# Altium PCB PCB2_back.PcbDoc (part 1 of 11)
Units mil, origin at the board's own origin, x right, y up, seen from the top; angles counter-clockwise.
Board outline 6299 x 3937 mil, 4 copper layers (TopLayer, GROUND, VCC, BottomLayer); 290 components, 470 nets, 2252 pads, 825 vias.
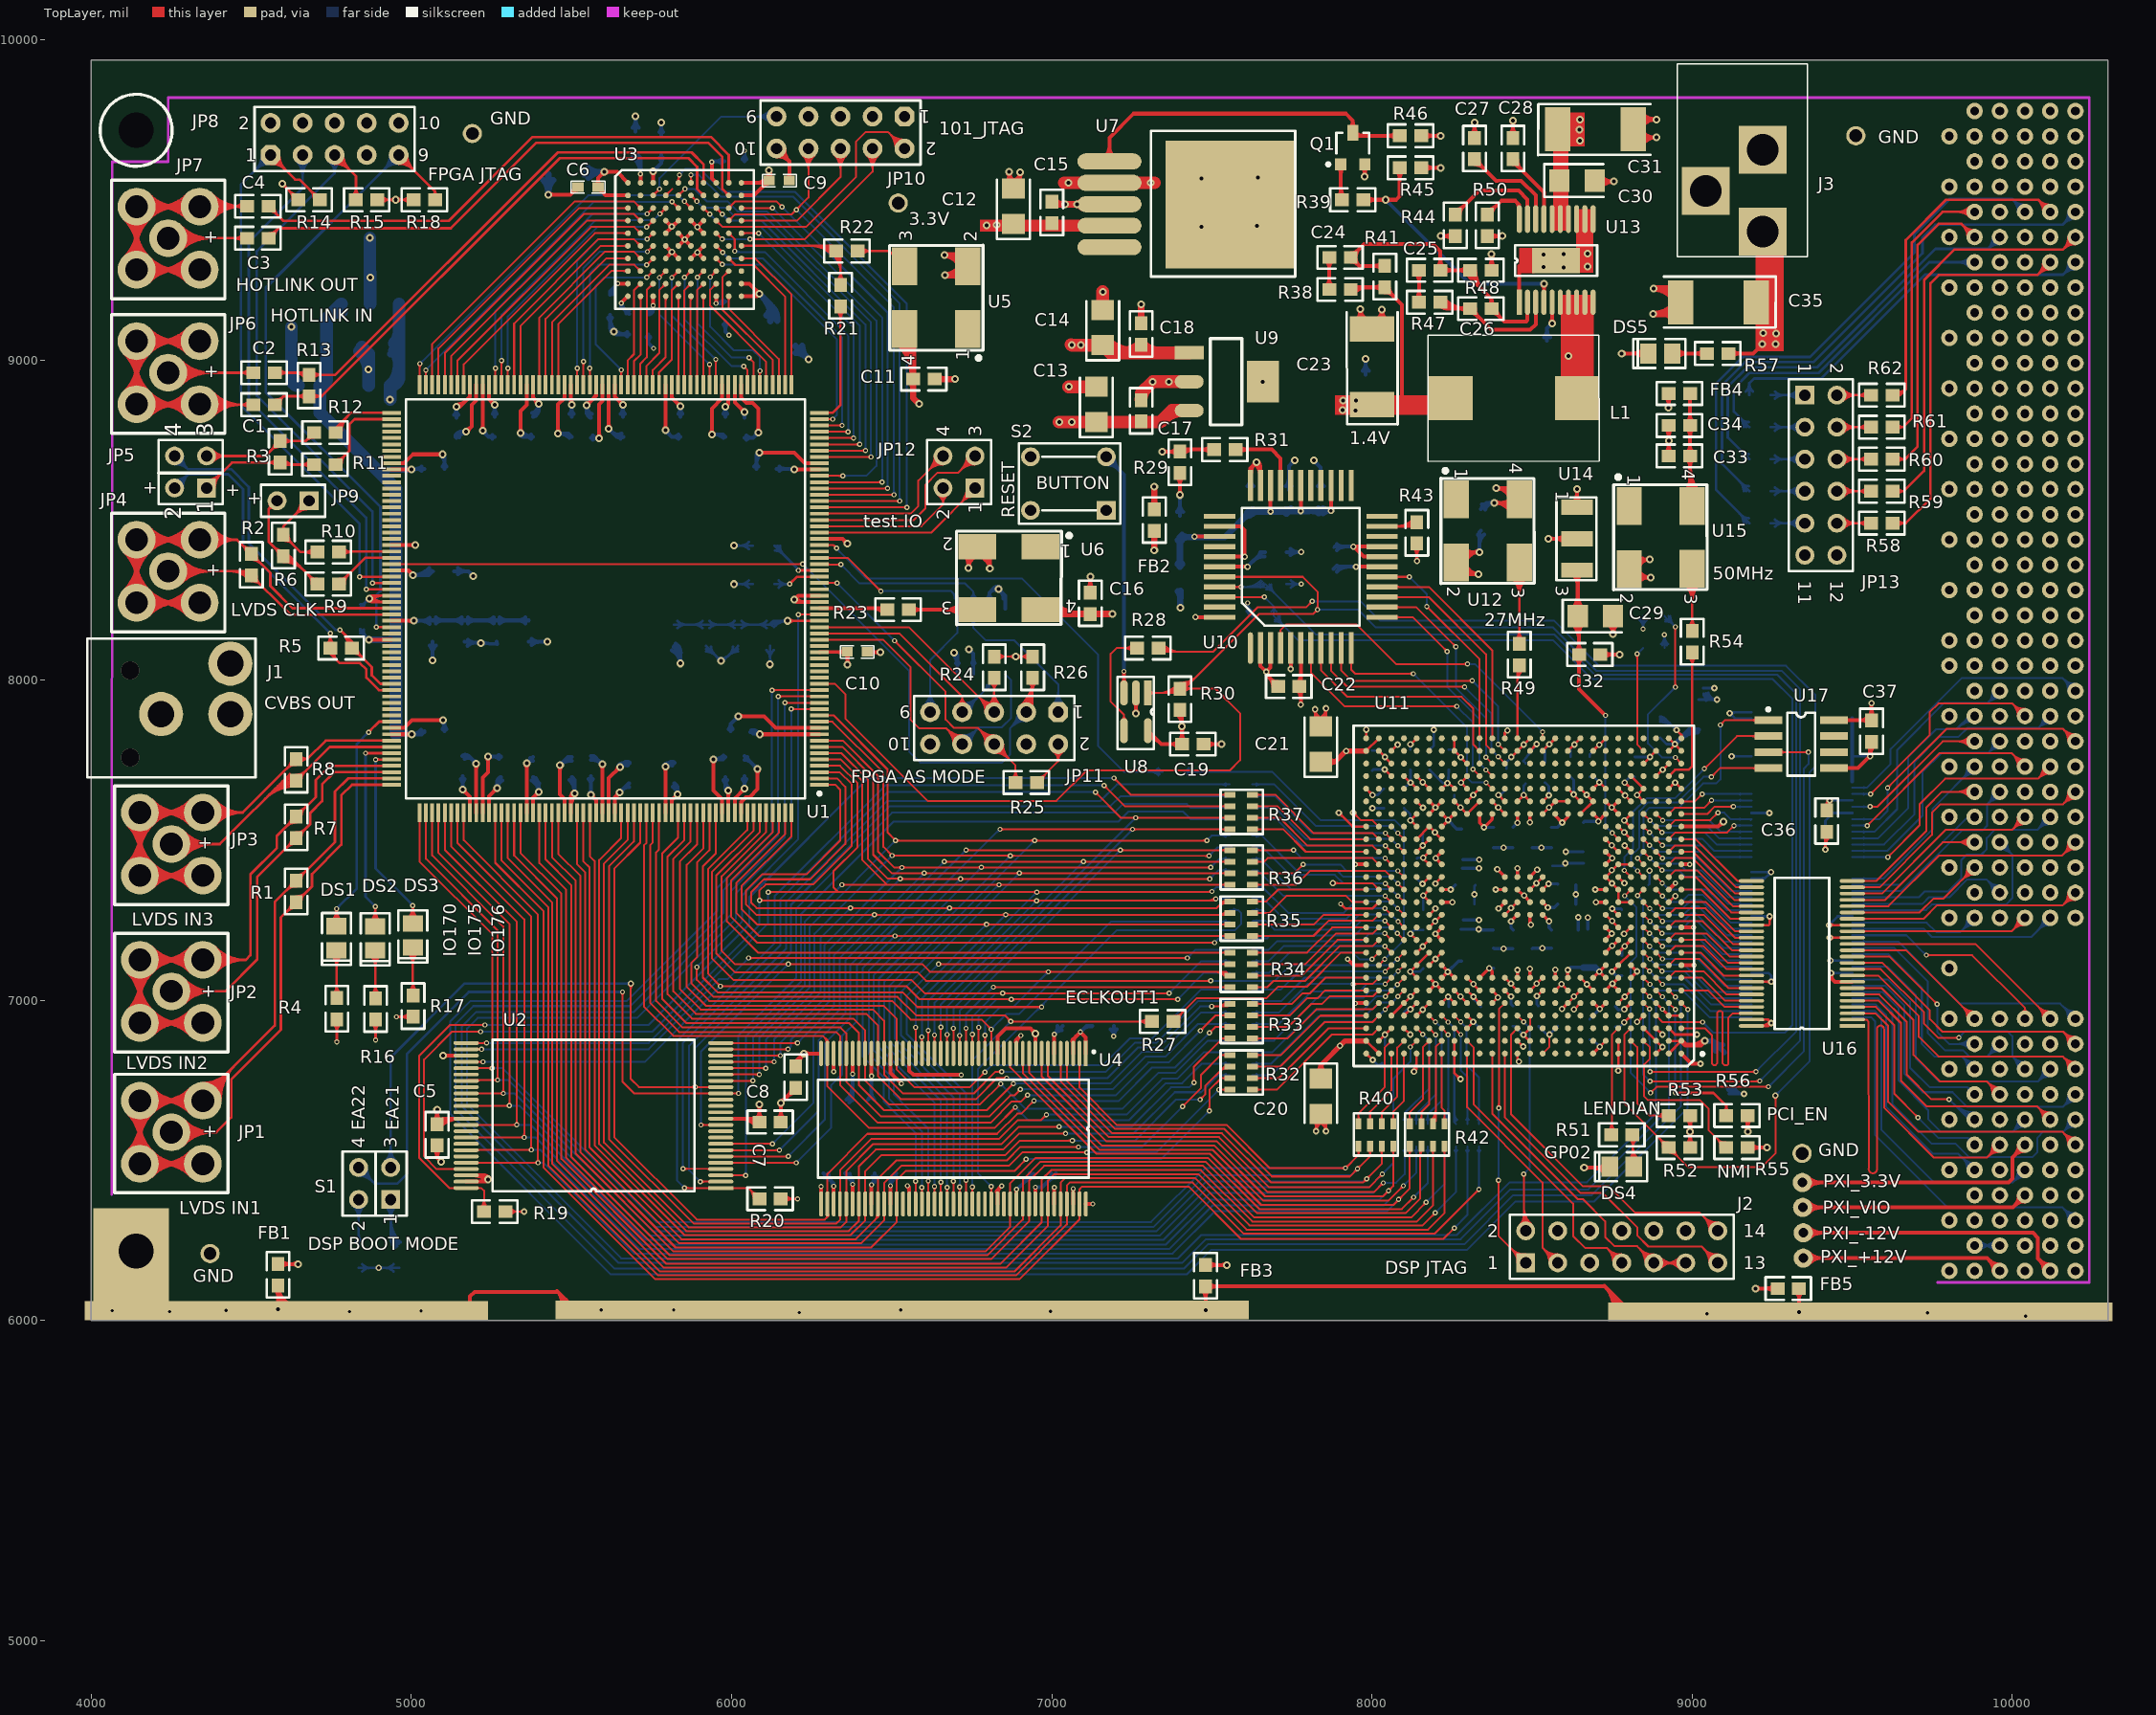
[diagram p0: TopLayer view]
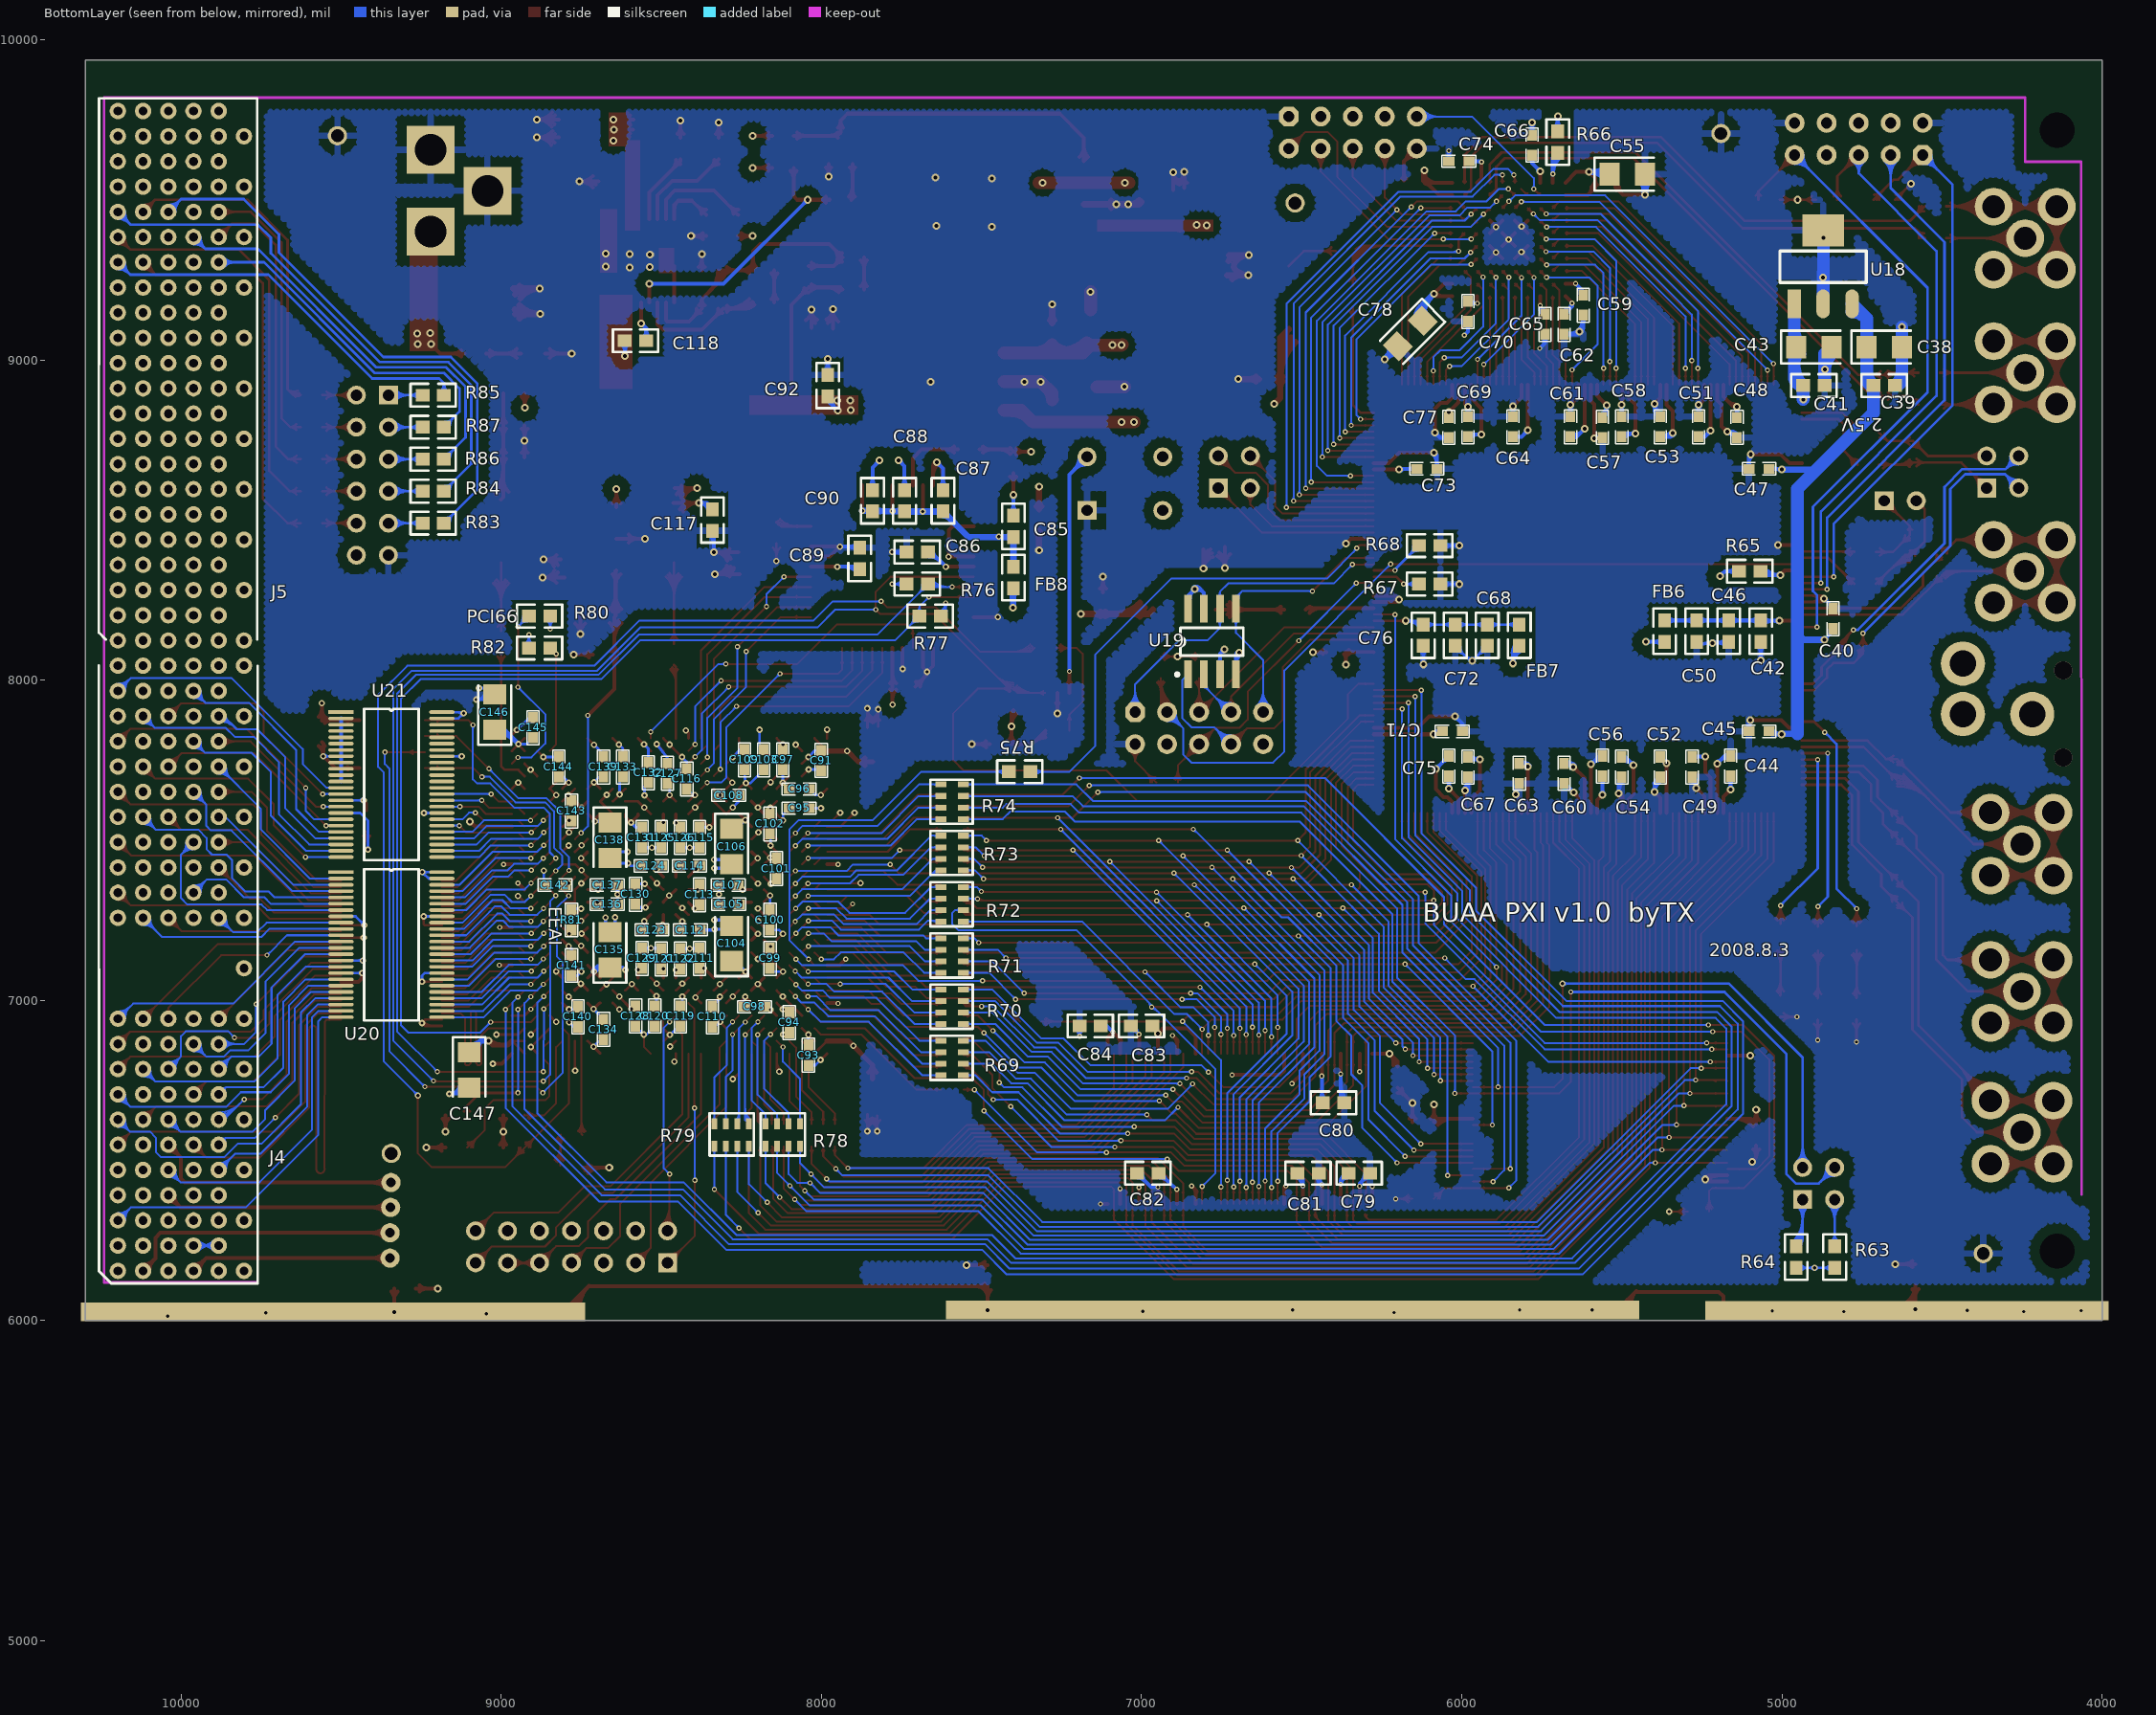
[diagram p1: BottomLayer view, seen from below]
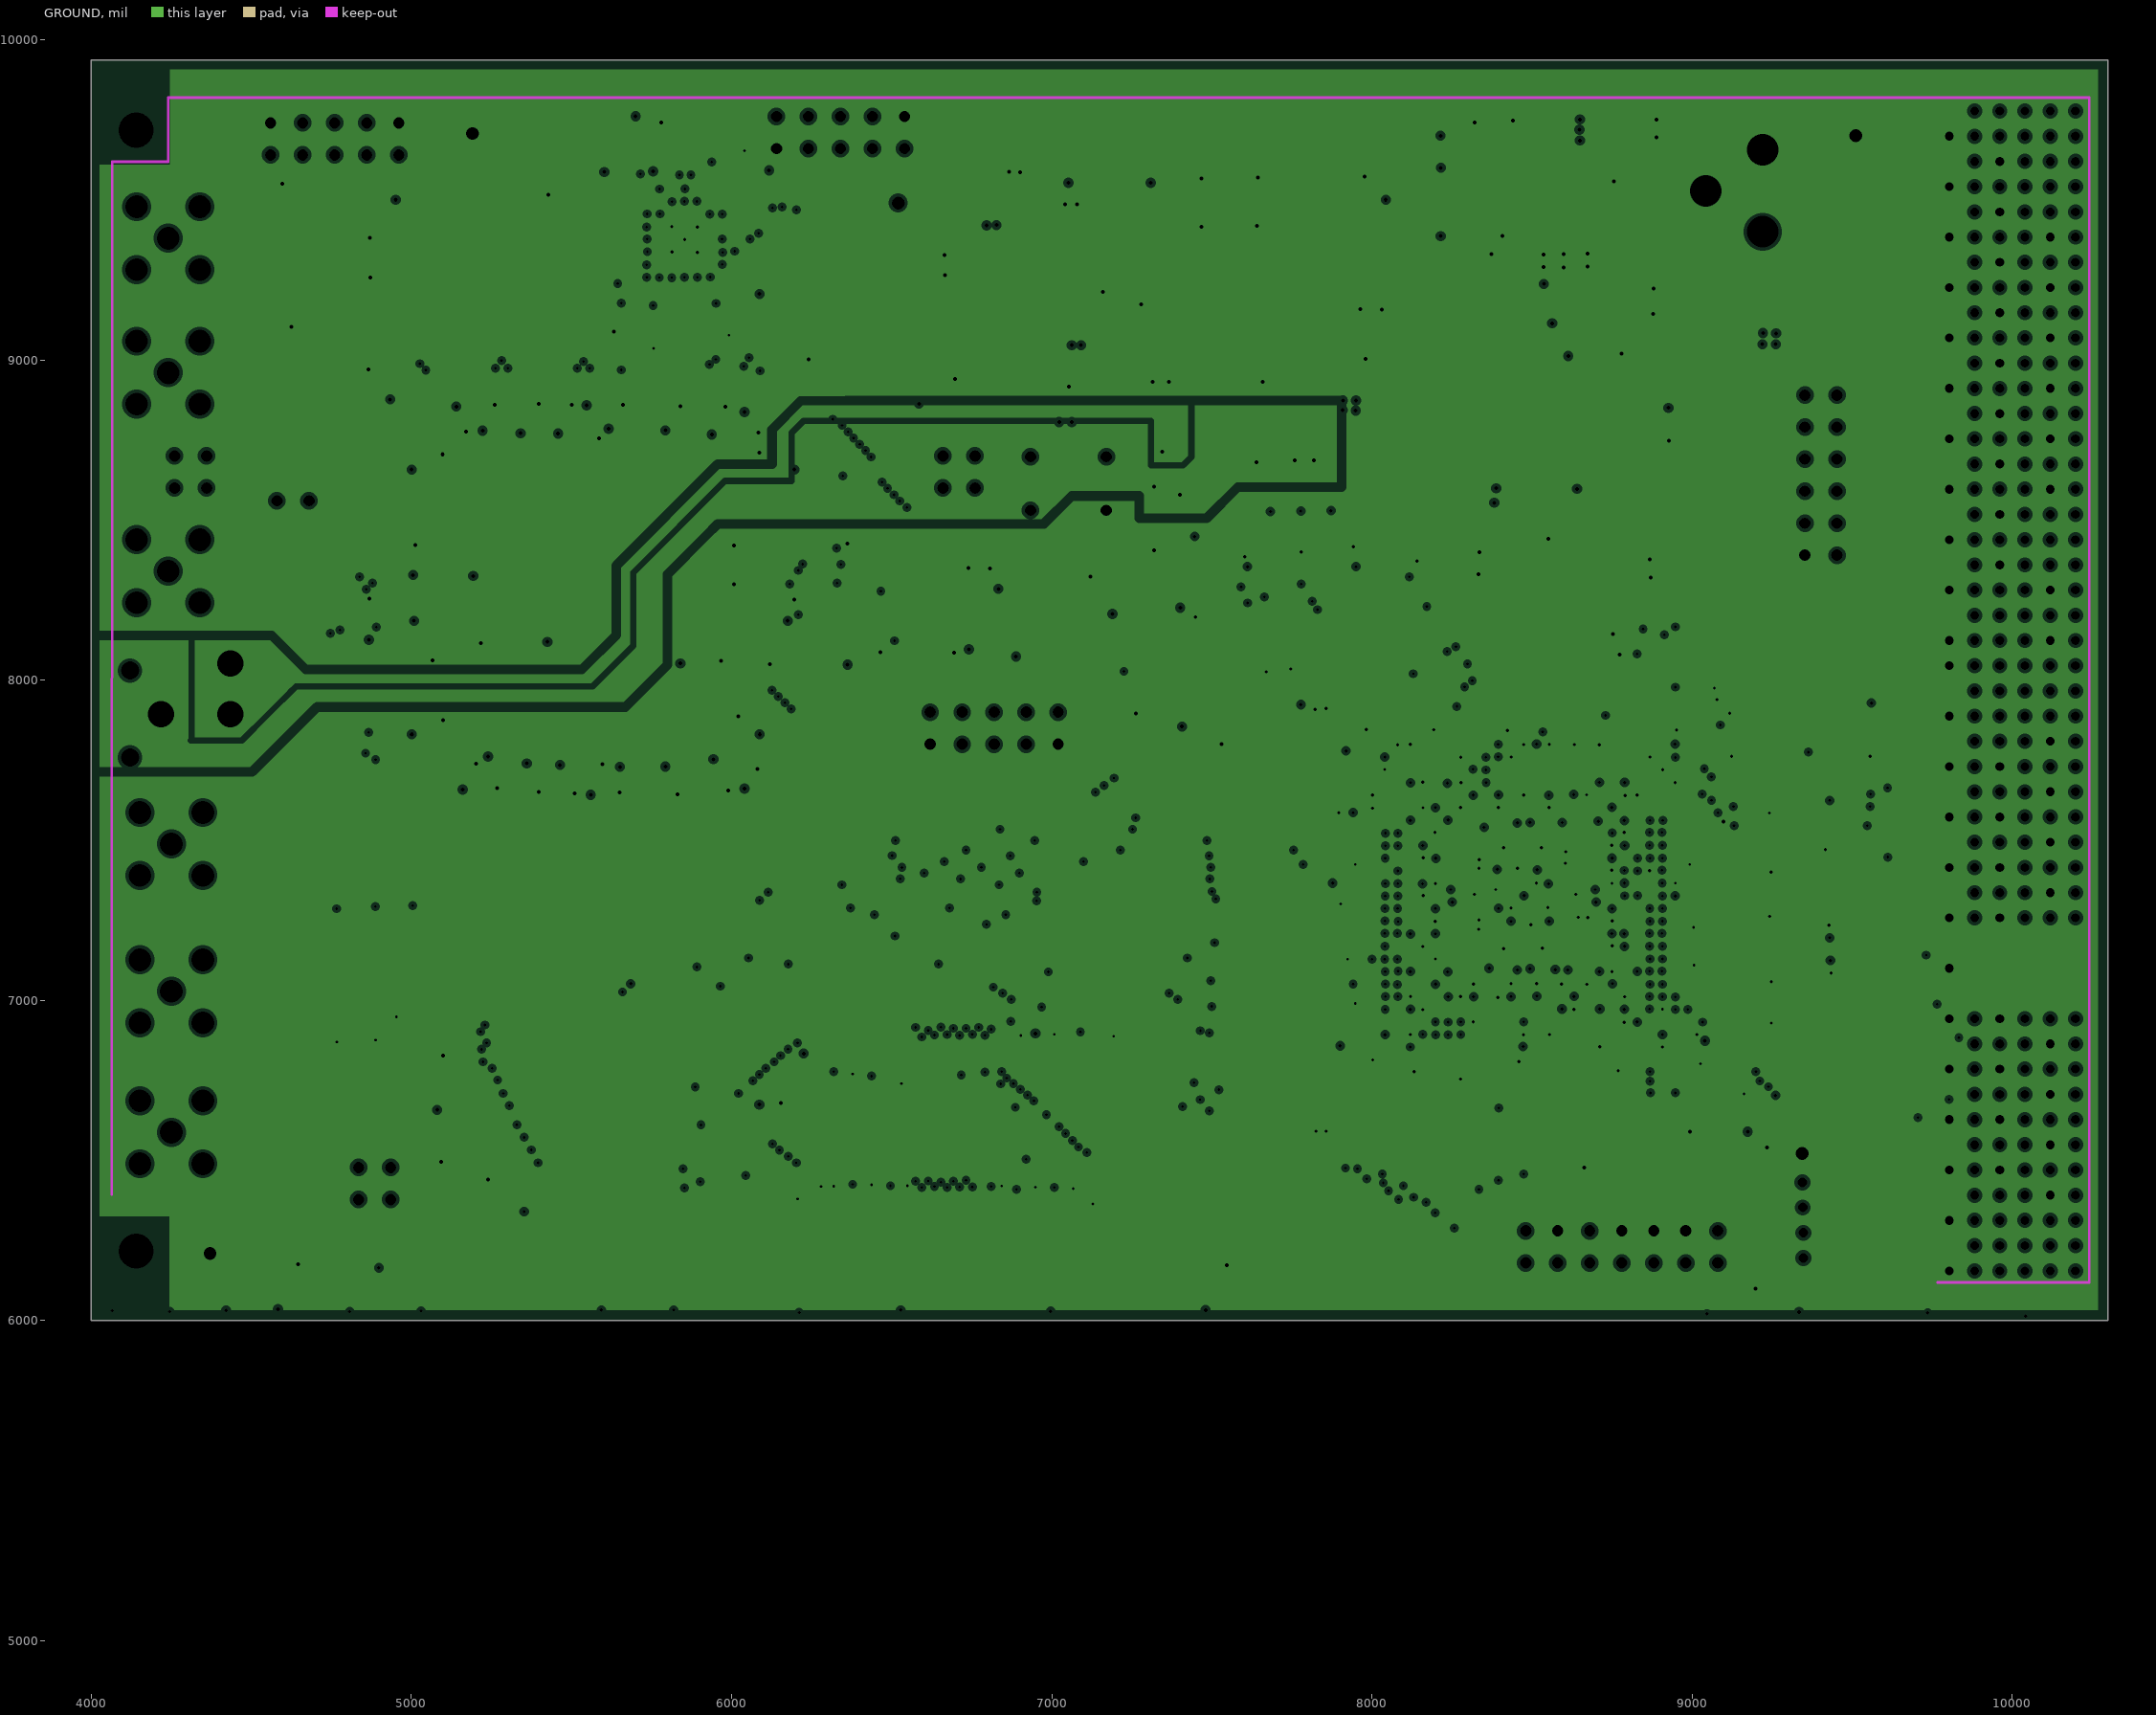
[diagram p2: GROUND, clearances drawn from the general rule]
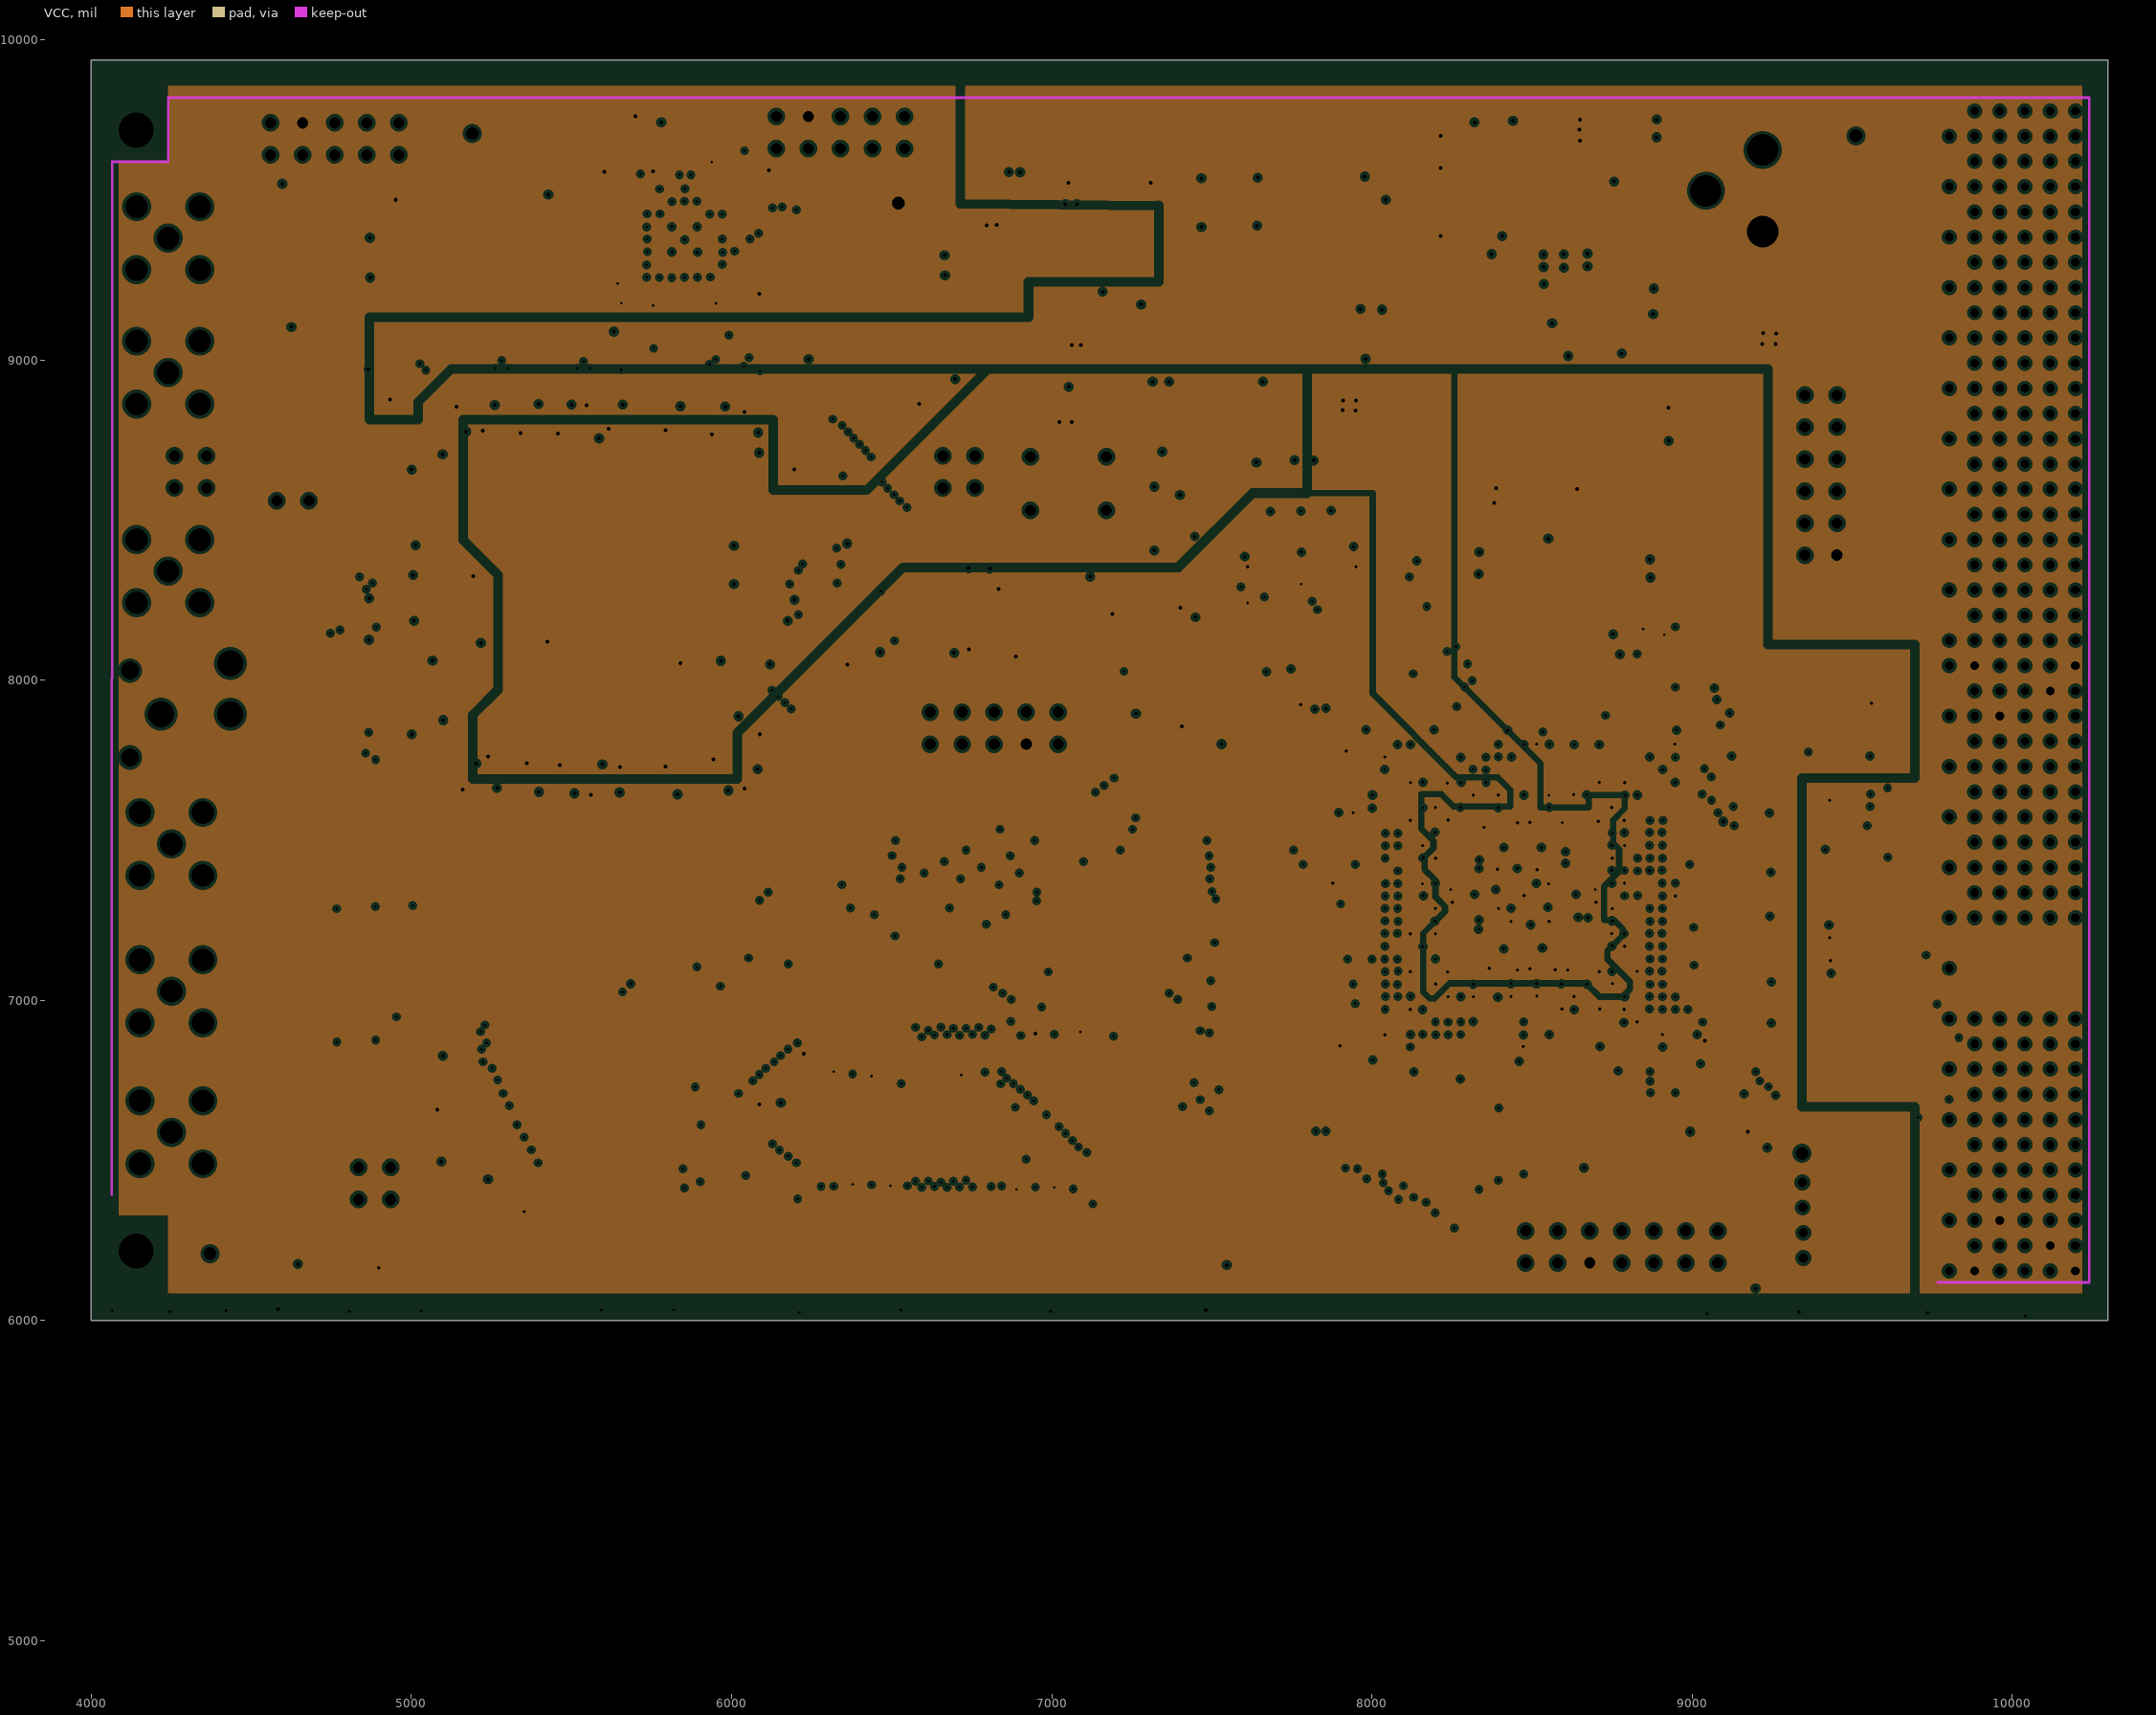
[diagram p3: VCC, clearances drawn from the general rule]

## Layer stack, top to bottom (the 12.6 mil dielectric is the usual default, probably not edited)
TopLayer: signal copper 1.4
Dielectric: core 12.6, FR-4, Dk 4.8
GROUND: plane copper 1.4, net (Multiple Nets)
Dielectric: prepreg 12.6, FR-4, Dk 4.8
VCC: plane copper 1.4, net (Multiple Nets)
Dielectric: core 12.6, FR-4, Dk 4.8
BottomLayer: signal copper 1.4

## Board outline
4000,6000 10299,6000 10299,9937 4000,9937

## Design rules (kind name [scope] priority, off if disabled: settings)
Clearance [All] p1: gap=6
ComponentClearance ComponentClearance_1 [All] p1: gap=10 collisioncheckmode=0
HoleSize HoleSize_1 [All] p1: absolutevalues=TRUE maxlimit=100 minlimit=1 maxpercent=80.000 minpercent=20.000
LayerPairs LayerPairs_1 [All] p1: enforce=TRUE
PasteMaskExpansion PasteMaskExpansion_1 [All] p1: expansion=0
PlaneClearance PlaneClearance_1 [All] p1: clearance=10
PlaneConnect [All] p1: planeconnectstyle=Relief reliefexpansion=15 reliefentries=4 reliefconductorwidth=15.75 reliefairgap=9.84
PolygonConnect PolygonConnect_1 [All] p1: connectstyle=Relief reliefconductorwidth=20 reliefentries=4 polygonreliefangle="90 Angle"
RoutingLayers [All] p1: top layer=Horizontal bottom layer=Vertical
RoutingPriority RoutingPriority_1 [All] p1: routingpriority=0
RoutingTopology RoutingTopology_1 [All] p1: topology=Shortest
RoutingVias [All] p1: holewidth=12 width=24 viastyle="Through Hole" minholewidth=8 minwidth=16 maxholewidth=28 maxwidth=50
ShortCircuit ShortCircuit_1 [All] p1: allowed=FALSE
SolderMaskExpansion SolderMaskExpansion_1 [All] p1: expansion=2
TestPointUsage TestPointUsage_1 [All] p1: valid=0 allowmultiple=FALSE
Testpoint Testpoint_1 [All] p1: side=7 testpointundercomponent=TRUE minsize=40 maxsize=100 preferedsize=60 minholesize=20 maxholesize=40 preferedholesize=32 testpointgrid=1 style=1001 order=-539222988
UnRoutedNet UnRoutedNet_1 [All] p1:
Width [All] p1: maxlimit=40 minlimit=6 preferedwidth=6
7 further rules are at their usual default settings.

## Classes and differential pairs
component class U_Sheet4_DSP2_videoport: C19 C22 C29 C32 C33 C34 C37 C85 C86 C87 C88 C89 C90 C117 DS4 FB2 FB4 FB8 J1 R28 R29 R30 R31 R43 R49 R51 R52 R53 R54 R55 R76 R77 R80 R81 R82 R? S2 U8 U10 U11 U12 U14 U15 U17
component class U_Sheet3_power_clock: C10 C12 C13 C14 C15 C17 C18 C20 C21 C23 C24 C25 C26 C27 C28 C30 C31 C35 C38 C39 C40 C41 C42 C43 C44 C45 C46 C47 C48 C49 C50 C51 C52 C53 C54 C56 C57 C58 C60 C61 C63 C64 C67 C68 C69 C71 C72 C73 C75 C76 C77 C91 C92 C93 C94 C95 C96 C97 C98 C99 C100 C101 C102 C103 C104 C105 C106 C107 C108 C109 C110 C111 C112 C113 C114 C115 C116 C118 C119 C120 C121 C122 C123 C124 C125 C126 C127 C128 C129 C130 C131 C132 C133 C134 C135 C136 C137 C138 C139 C140 C141 C142 C143 C144 C145 C146 C147 DS5 FB6 FB7 J3 L1 Q1 R38 R39 R41 R44 R45 R46 R47 R48 R50 R57 U7 U9 U13 U18
component class U_Sheet2_PXI: C36 J4 J5 JP13 R56 R58 R59 R60 R61 R62 R83 R84 R85 R86 R87 U16 U20 U21
component class U_Sheet2_DSP_EMIF: C5 C7 C8 C79 C80 C81 C82 C83 C84 J2 R19 R20 R27 R32 R33 R34 R35 R36 R37 R40 R42 R63 R64 R69 R70 R71 R72 R73 R74 R78 R79 S1 U2 U4
component class U_Sheet1_FPGA2: C1 C2 C3 C4 C6 C9 C11 C16 C55 C59 C62 C65 C66 C70 C74 C78 DS1 DS2 DS3 FB1 FB3 FB5 JP1 JP2 JP3 JP4 JP5 JP6 JP7 JP8 JP9 JP10 JP11 JP12 L2 R1 R2 R3 R4 R5 R6 R7 R8 R9 R10 R11 R12 R13 R14 R15 R16 R17 R18 R21 R22 R23 R24 R25 R26 R65 R66 R67 R68 R75 U1 U3 U5 U6 U19

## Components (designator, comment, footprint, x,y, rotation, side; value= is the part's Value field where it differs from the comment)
C1 "Cap" C1608-0603 4540,8860 r180 top
C2 "Cap" C1608-0603 4540,8960 r180 top
C3 "Cap" C1608-0603 4520,9380 r180 top
C4 "Cap" C1608-0603 4520,9480 r180 top
C5 "Cap" C1608-0603 5080,6580 r90 top (schematic designator C19)
C6 "Cap" 0603 5520,9540 r0 top (schematic designator C9)
C7 "Cap" C1608-0603 6120,6620 r0 top (schematic designator C27)
C8 "Cap" C1608-0603 6200,6760 r90 top (schematic designator C20)
C9 "Cap" 0603 6180,9560 r180 top (schematic designator C7)
C10 "Cap" 0603 6361,8088 r0 top (schematic designator C104)
C11 "Cap" C1608-0603 6600,8940 r180 top (schematic designator C18)
C12 "Cap Pol1" CC3216-1206 6880,9480 r90 top (schematic designator C135)
C13 "Cap Pol1" CC3216-1206 7139,8861 r90 top (schematic designator C137)
C14 "Cap Pol1" CC3216-1206 7159,9101 r90 top (schematic designator C136)
C15 "Cap" C1608-0603 7000,9460 r270 top (schematic designator C95)
C16 "Cap" C1608-0603 7120,8240 r270 top (schematic designator C17)
C17 "Cap" C1608-0603 7279,8841 r270 top (schematic designator C125)
C18 "Cap" C1608-0603 7279,9081 r270 top (schematic designator C96)
C19 "Cap" C1608-0603 7440,7800 r180 top (schematic designator C133)
C20 "Cap Pol2" CC3216-1206 7840,6700 r270 top (schematic designator C150)
C21 "Cap Pol2" CC3216-1206 7840,7800 r90 top (schematic designator C147)
C22 "Cap" C1608-0603 7740,7980 r0 top (schematic designator C156)
C23 "Cap Pol1" CC6032 8000,8860 r90 top (schematic designator C138)
C24 "Cap" C1608-0603 7900,9320 r180 top (schematic designator C122)
C25 "Cap" C1608-0603 8180,9280 r180 top (schematic designator C113)
C26 "Cap" C1608-0603 8340,9160 r180 top (schematic designator C118)
C27 "Cap" C1608-0603 8320,9660 r270 top (schematic designator C54)
C28 "Cap" C1608-0603 8440,9660 r270 top (schematic designator C64)
C29 "Cap Pol2" CC3216-1206 8697.68,8200 r0 top (schematic designator C164)
C30 "Cap Pol2" CC3216-1206 8640,9560 r0 top (schematic designator C146)
C31 "Cap Pol1" CC6032 8580,9720 r0 top (schematic designator C134)
C32 "Cap" C1608-0603 8680,8080 r180 top (schematic designator C163)
C33 "Cap" C1608-0603 8960,8700 r0 top (schematic designator C161)
C34 "Cap" C1608-0603 8960,8795 r0 top (schematic designator C160)
C35 "Cap Pol1" CC6032 9200,9180 r180 top (schematic designator C140)
C36 "Cap" C1608-0603 9420,7560 r90 top (schematic designator C166)
C37 "Cap" C1608-0603 9560,7840 r90 top (schematic designator C162)
C38 "Cap Pol1" CC3216-1206 4680,9040 r180 bottom (schematic designator C143)
C39 "Cap" C1608-0603 4680,8920 r0 bottom (schematic designator C132)
C40 "Cap" 0603 4840,8160 r90 bottom (schematic designator C108)
C41 "Cap" C1608-0603 4900,8920 r0 bottom (schematic designator C127)
C42 "Cap" C1608-0603 5066,8153 r90 bottom (schematic designator C131)
C43 "Cap Pol1" CC3216-1206 4900,9040 r180 bottom (schematic designator C139)
C44 "Cap" 0603 5160,7700 r90 bottom (schematic designator C98)
C45 "Cap" 0603 5040,7840 r0 bottom (schematic designator C97)
C46 "Cap" C1608-0603 5166,8153 r90 bottom (schematic designator C129)
C47 "Cap" 0603 5040,8660 r0 bottom (schematic designator C103)
C48 "Cap" 0603 5140,8820 r270 bottom (schematic designator C110)
C49 "Cap" 0603 5280,7760 r270 bottom (schematic designator C100)
C50 "Cap Pol1" C1608-0603 5266,8153 r270 bottom (schematic designator C142)
C51 "Cap" 0603 5260,8760 r90 bottom (schematic designator C124)
C52 "Cap" 0603 5380,7760 r270 bottom (schematic designator C106)
C53 "Cap" 0603 5380,8760 r90 bottom (schematic designator C112)
C54 "Cap" 0603 5500,7760 r270 bottom (schematic designator C111)
C55 "Cap Pol2" CC3216-1206 5482.31,9580 r180 bottom (schematic designator C14)
C56 "Cap" 0603 5560,7700 r90 bottom (schematic designator C109)
C57 "Cap" 0603 5560,8820 r270 bottom (schematic designator C114)
C58 "Cap" 0603 5500,8760 r90 bottom (schematic designator C101)
C59 "Cap" 0603 5620,9140 r90 bottom (schematic designator C10)
C60 "Cap" 0603 5680,7740 r270 bottom (schematic designator C116)
C61 "Cap" 0603 5660,8760 r90 bottom (schematic designator C121)
C62 "Cap" 0603 5680,9080 r90 bottom (schematic designator C6)
C63 "Cap" 0603 5820,7740 r270 bottom (schematic designator C123)
C64 "Cap" 0603 5840,8760 r90 bottom (schematic designator C117)
C65 "Cap" 0603 5740,9080 r90 bottom (schematic designator C5)
C66 "Cap" 0603 5780,9702 r270 bottom (schematic designator C11)
C67 "Cap" 0603 5980,7760 r270 bottom (schematic designator C120)
C68 "Cap" C1608-0603 5920,8140 r90 bottom (schematic designator C128)
C69 "Cap" 0603 5980,8760 r90 bottom (schematic designator C107)
C70 "Cap" 0603 5980,9120 r90 bottom (schematic designator C16)
C71 "Cap" 0603 6060,7840 r180 bottom (schematic designator C119)
C72 "Cap Pol1" C1608-0603 6020,8140 r270 bottom (schematic designator C141)
C73 "Cap" 0603 6140,8660 r180 bottom (schematic designator C115)
C74 "Cap" 0603 6040,9620 r180 bottom (schematic designator C8)
C75 "Cap" 0603 6040,7700 r90 bottom (schematic designator C105)
C76 "Cap" C1608-0603 6120,8140 r90 bottom (schematic designator C130)
C77 "Cap" 0603 6040,8820 r270 bottom (schematic designator C99)
C78 "Cap Pol2" CC3216-1206 6160,9082.32 r315 bottom (schematic designator C15)
C79 "Cap" C1608-0603 6320,6460 r0 bottom (schematic designator C24)
C80 "Cap" C1608-0603 6400,6680 r0 bottom (schematic designator C21)
C81 "Cap" C1608-0603 6480,6460 r0 bottom (schematic designator C25)
C82 "Cap" C1608-0603 6980,6460 r180 bottom (schematic designator C26)
C83 "Cap" C1608-0603 7000,6920 r180 bottom (schematic designator C23)
C84 "Cap" C1608-0603 7160,6920 r180 bottom (schematic designator C22)
C85 "Cap" C1608-0603 7400,8480 r270 bottom (schematic designator C159)
C86 "Cap" C1608-0603 7700,8400 r180 bottom (schematic designator C158)
C87 "Cap" C1608-0603 7620,8560 r270 bottom (schematic designator C157)
C88 "Cap" C1608-0603 7740,8560 r270 bottom (schematic designator C155)
C89 "Cap" C1608-0603 7880,8380 r270 bottom (schematic designator C154)
C90 "Cap" C1608-0603 7840,8560 r270 bottom (schematic designator C153)
C91 "Cap" 0603 8000,7780 r270 bottom (schematic designator C49)
C92 "Cap" C1608-0603 7980,8920 r270 bottom (schematic designator C126)
C93 "Cap" 0603 8040,6860 r270 bottom (schematic designator C75)
C94 "Cap" 0603 8100,6962 r270 bottom (schematic designator C74)
C95 "Cap" 0603 8100,7600 r180 bottom (schematic designator C57)
C96 "Cap" 0603 8100,7660 r180 bottom (schematic designator C65)
C97 "Cap" 0603 8120,7720 r90 bottom (schematic designator C58)
C98 "Cap" 0603 8240,6980 r180 bottom (schematic designator C73)
C99 "Cap" 0603 8160,7100 r90 bottom (schematic designator C69)
C100 "Cap" 0603 8160,7220 r90 bottom (schematic designator C68)
C101 "Cap" 0603 8140,7380 r90 bottom (schematic designator C67)
C102 "Cap" 0603 8160,7520 r90 bottom (schematic designator C66)
C103 "Cap" 0603 8180,7720 r90 bottom (schematic designator C40)
C104 "Cap Pol2" CC3216-1206 8280,7177.69 r90 bottom (schematic designator C149)
C105 "Cap" 0603 8320,7300 r180 bottom (schematic designator C63)
C106 "Cap Pol2" CC3216-1206 8280,7480 r270 bottom (schematic designator C148)
C107 "Cap" 0603 8260,7360 r0 bottom (schematic designator C71)
C108 "Cap" 0603 8320,7640 r180 bottom (schematic designator C59)
C109 "Cap" 0603 8240,7720 r90 bottom (schematic designator C56)
C110 "Cap" 0603 8340,6980 r270 bottom (schematic designator C76)
C111 "Cap" 0603 8380,7100 r90 bottom (schematic designator C79)
C112 "Cap" 0603 8378,7220 r0 bottom (schematic designator C78)
C113 "Cap" 0603 8380,7298 r90 bottom (schematic designator C72)
C114 "Cap" 0603 8380,7420 r0 bottom (schematic designator C60)
C115 "Cap" 0603 8380,7540 r270 bottom (schematic designator C53)
C116 "Cap" 0603 8420,7660 r90 bottom (schematic designator C48)
C117 "Cap" C1608-0603 8340,8500 r90 bottom (schematic designator C165)
C118 "Cap" C1608-0603 8580,9060 r0 bottom (schematic designator C102)
C119 "Cap" 0603 8440,6982 r270 bottom (schematic designator C83)
C120 "Cap" 0603 8520,6982 r270 bottom (schematic designator C77)
C121 "Cap" 0603 8500,7098 r90 bottom (schematic designator C81)
C122 "Cap" 0603 8440,7098 r90 bottom (schematic designator C80)
C123 "Cap" 0603 8560,7220 r180 bottom (schematic designator C70)
C124 "Cap" 0603 8500,7420 r0 bottom (schematic designator C52)
C125 "Cap" 0603 8500,7540 r270 bottom (schematic designator C43)
C126 "Cap" 0603 8440,7540 r270 bottom (schematic designator C42)
C127 "Cap" 0603 8480,7740 r270 bottom (schematic designator C37)
C128 "Cap" 0603 8580,6982 r270 bottom (schematic designator C82)
C129 "Cap" 0603 8560,7100 r90 bottom (schematic designator C87)
C130 "Cap" 0603 8580,7300 r90 bottom (schematic designator C90)
C131 "Cap" 0603 8560,7540 r270 bottom (schematic designator C51)
C132 "Cap" 0603 8540,7680 r90 bottom (schematic designator C46)
C133 "Cap" 0603 8620,7698 r90 bottom (schematic designator C39)
C134 "Cap" 0603 8680,6940 r270 bottom (schematic designator C86)
C135 "Cap Pol2" CC3216-1206 8660,7157.69 r90 bottom (schematic designator C151)
C136 "Cap" 0603 8700,7300 r180 bottom (schematic designator C50)
C137 "Cap" 0603 8700,7360 r180 bottom (schematic designator C44)
C138 "Cap Pol2" CC3216-1206 8660,7500 r270 bottom (schematic designator C145)
C139 "Cap" 0603 8680,7698 r90 bottom (schematic designator C38)
C140 "Cap" 0603 8760,6980 r270 bottom (schematic designator C85)
C141 "Cap" 0603 8780,7140 r270 bottom (schematic designator C84)
C142 "Cap" 0603 8800,7360 r0 bottom (schematic designator C47)
C143 "Cap" 0603 8780,7560 r90 bottom (schematic designator C55)
C144 "Cap" 0603 8820,7698 r90 bottom (schematic designator C41)
C145 "Cap" 0603 8900,7820 r90 bottom (schematic designator C45)
C146 "Cap Pol2" CC3216-1206 9020,7900 r90 bottom (schematic designator C144)
C147 "Cap Pol2" CC3216-1206 9100,6782.31 r270 bottom (schematic designator C152)
DS1 "LED2" "SMD _LED" 4766,7194 r90 top (schematic designator DS3)
DS2 "LED2" "SMD _LED" 4887,7193 r90 top
DS3 "LED2" "SMD _LED" 5004,7202 r90 top (schematic designator DS1)
DS4 "LED3" "SMD _LED" 8780,6480 r0 top (schematic designator DS9)
DS5 "LED3" "SMD _LED" 8900,9020 r0 top (schematic designator DS6)
FB1 "FB" C1608-0603 4583,6143 r90 top (schematic designator FB8)
FB2 "BLM18PG121SN1" C1608-0603 7320,8500 r270 top (schematic designator FB5)
FB3 "FB" C1608-0603 7480,6140 r90 top (schematic designator FB7)
FB4 "BLM18PG121SN1" C1608-0603 8960,8895 r0 top (schematic designator FB3)
FB5 "FB" C1608-0603 9300,6100 r180 top (schematic designator FB6)
FB6 "FB" C1608-0603 5366,8153 r90 bottom (schematic designator FB2)
FB7 "FB" C1608-0603 5820,8140 r90 bottom (schematic designator FB1)
FB8 "BLM18PG121SN1" C1608-0603 7400,8320 r270 bottom (schematic designator FB4)
J1 "RCA" RCA 4260,7940 r0 top (schematic designator J4)
J2 "Header 7X2 JTAG" HDR2X7 8480,6180 r0 top (schematic designator J1)
J3 "PWP_CON" POWER_CON 9220,9400 r90 top
J4 "352068-1" PCI2-H123 10000,7100.06 r270 bottom (schematic designator J2)
J5 "352152-1" PCI2-H121 10000,8950.46 r270 bottom
JP1 "Header 2" SMA 4250,6588 r0 top
JP2 "Header 2" SMA 4250,7028 r0 top
JP3 "Header 2" SMA 4250,7488 r0 top (schematic designator JP7)
JP4 "Header 2" SMA 4240,8340 r0 top (schematic designator JP11)
JP5 "Header 2X2" HDR2X2 4360,8600 r90 top (schematic designator JP10)
JP6 "Header 2" SMA 4240,8960 r0 top (schematic designator JP8)
JP7 "Header 2" SMA 4240,9380 r0 top (schematic designator JP9)
JP8 "JTAG" HDR2X5 4560,9640 r0 top (schematic designator JP4)
JP9 "Header 2" HDR1X2 4680,8560 r180 top (schematic designator JP13)
JP10 "101_JTAG" HDR2X5 6540,9760 r180 top (schematic designator JP3)
JP11 "AS mode" HDR2X5 7020,7900 r180 top (schematic designator JP5)
JP12 "Header 2X2" HDR2X2 6760,8600 r90 top
JP13 "Header 6X2" HDR2X6 9352,8890 r270 top (schematic designator JP6)
L1 "Inductor Iron" L44.7uH 8640,8880 r180 top
Q1 "QNPN3904" "SO-G3 for NPN" 7940,9660 r0 top
R1 "Res2" C1608-0603 4640,7340 r270 top (schematic designator R43)
R2 "Res2" C1608-0603 4500,8360 r270 top (schematic designator R4)
R3 "Res2" C1608-0603 4590,8713 r270 top (schematic designator R1)
R4 "Res2" C1608-0603 4767,6974 r270 top (schematic designator R19)
R5 "Res2" C1608-0603 4780,8100 r180 top (schematic designator R46)
R6 "Res2" C1608-0603 4600,8420 r270 top (schematic designator R5)
R7 "Res2" C1608-0603 4640,7540 r270 top (schematic designator R42)
R8 "Res2" C1608-0603 4640,7720 r270 top (schematic designator R77)
R9 "Res2" C1608-0603 4740,8300 r0 top (schematic designator R6)
R10 "Res2" C1608-0603 4740,8400 r0 top (schematic designator R7)
R11 "Res2" C1608-0603 4730,8673 r0 top (schematic designator R2)
R12 "Res2" C1608-0603 4730,8773 r0 top (schematic designator R3)
R13 "Res2" C1608-0603 4680,8920 r270 top (schematic designator R11)
R14 "Res2" C1608-0603 4680,9500 r0 top (schematic designator R17)
R15 "Res2" C1608-0603 4860,9500 r0 top (schematic designator R16)
R16 "Res2" C1608-0603 4888,6973 r270 top (schematic designator R18)
R17 "Res2" C1608-0603 5005,6982 r270 top (schematic designator R15)
R18 "Res2" C1608-0603 5040,9500 r180 top (schematic designator R14)
R19 "Res1" CR1608-0603 5260,6340 r0 top (schematic designator R58)
R20 "Res1" CR1608-0603 6120,6380 r180 top (schematic designator R59)
R21 "Res2" C1608-0603 6340,9200 r270 top (schematic designator R13)
R22 "Res2" C1608-0603 6360,9340 r180 top (schematic designator R25)
R23 "Res2" C1608-0603 6520,8220 r180 top (schematic designator R24)
R24 "Res2" C1608-0603 6820,8040 r90 top (schematic designator R27)
R25 "Res2" C1608-0603 6920,7680 r180 top (schematic designator R28)
R26 "Res2" C1608-0603 6940,8040 r90 top
R27 "Res1" CR1608-0603 7346,6934 r180 top (schematic designator R55)
R28 "Res1" CR1608-0603 7300,8100 r0 top (schematic designator R81)
R29 "Res1" CR1608-0603 7400,8680 r90 top (schematic designator R41)
R30 "Res1" CR1608-0603 7400,7940 r270 top (schematic designator R71)
R31 "Res1" CR1608-0603 7540,8720 r180 top (schematic designator R40)
R32 "R0604_4" R0603_4 7626,6721 r180 top (schematic designator R38)
R33 "R0604_4" R0603_4 7626,6881 r180 top (schematic designator R37)
R34 "R0604_4" R0603_4 7626,7041 r180 top (schematic designator R30)
R35 "R0604_4" R0603_4 7626,7201 r180 top (schematic designator R54)
R36 "R0604_4" R0603_4 7626,7361 r180 top (schematic designator R49)
R37 "R0604_4" R0603_4 7626,7534 r180 top (schematic designator R51)
R38 "Res1" CR1608-0603 7900,9220 r0 top (schematic designator R69)
R39 "Res3" CR1608-0603 7940,9500 r0 top (schematic designator R72)
R40 "R0604_4" R0603_4 8066,6614 r270 top (schematic designator R31)
R41 "Res1" CR1608-0603 8040,9260 r270 top (schematic designator R70)
R42 "R0604_4" R0603_4 8226,6614 r270 top (schematic designator R32)
R43 "Res1" CR1608-0603 8140,8460 r270 top (schematic designator R39)
R44 "Res1" CR1608-0603 8260,9420 r270 top (schematic designator R66)
R45 "Res1" CR1608-0603 8120,9600 r180 top (schematic designator R64)
R46 "Res3" CR1608-0603 8120,9700 r0 top (schematic designator R73)
R47 "Res1" CR1608-0603 8180,9180 r0 top (schematic designator R68)
R48 "Res1" CR1608-0603 8340,9280 r180 top (schematic designator R67)
R49 "Res1" CR1608-0603 8460,8080 r270 top (schematic designator R76)
R50 "Res1" CR1608-0603 8360,9420 r90 top (schematic designator R65)
R51 "Res1" CR1608-0603 8780,6580 r0 top (schematic designator R86)
R52 "Res1" CR1608-0603 8960,6540 r180 top (schematic designator R83)
R53 "Res1" CR1608-0603 8960,6640 r180 top (schematic designator R84)
R54 "Res1" CR1608-0603 9000,8120 r270 top (schematic designator R82)
R55 "Res1" CR1608-0603 9140,6540 r180 top (schematic designator R79)
R56 "Res1" CR1608-0603 9140,6640 r0 top (schematic designator R61)
R57 "Res2" CR1608-0603 9080,9020 r0 top (schematic designator R62)
R58 "Res1" CR1608-0603 9592,8490 r180 top (schematic designator R91)
R59 "Res1" CR1608-0603 9592,8590 r180 top (schematic designator R90)
R60 "Res1" CR1608-0603 9592,8690 r180 top (schematic designator R89)
R61 "Res1" CR1608-0603 9592,8790 r180 top (schematic designator R85)
R62 "Res1" CR1608-0603 9592,8890 r180 top (schematic designator R75)
R63 "Res1" CR1608-0603 4835,6198 r90 bottom (schematic designator R57)
R64 "Res1" CR1608-0603 4955,6198 r90 bottom (schematic designator R56)
R65 "Res2" C1608-0603 5100,8340 r0 bottom (schematic designator R29)
R66 "Res2" C1608-0603 5700,9680 r90 bottom (schematic designator R8)
R67 "Res2" C1608-0603 6100,8300 r0 bottom (schematic designator R22)
R68 "Res2" C1608-0603 6100,8420 r0 bottom (schematic designator R23)
R69 "R0604_4" R0603_4 7626,6874 r180 bottom (schematic designator R36)
R70 "R0604_4" R0603_4 7626,7034 r180 bottom (schematic designator R35)
R71 "R0604_4" R0603_4 7626,7194 r180 bottom (schematic designator R52)
R72 "R0604_4" R0603_4 7626,7354 r180 bottom (schematic designator R47)
R73 "R0604_4" R0603_4 7626,7514 r180 bottom (schematic designator R48)
R74 "R0604_4" R0603_4 7626,7674 r180 bottom (schematic designator R50)
R75 "Res1" CR1608-0603 7380,7714 r0 bottom (schematic designator R12)
R76 "Res1" CR1608-0603 7700,8300 r180 bottom (schematic designator R87)
R77 "Res1" CR1608-0603 7660,8200 r0 bottom (schematic designator R88)
R78 "R0604_4" R0603_4 8066,6614 r270 bottom (schematic designator R33)
R79 "R0604_4" R0603_4 8226,6614 r270 bottom (schematic designator R34)
R80 "Res1" CR1608-0603 8880,8200 r180 bottom (schematic designator R74)
R81 "Res1" 0603 8780,7220 r90 bottom (schematic designator R78)
R82 "Res1" CR1608-0603 8880,8100 r0 bottom (schematic designator R80)
R83 "Res1" CR1608-0603 9212,8490 r180 bottom (schematic designator R63)
R84 "Res1" CR1608-0603 9212,8590 r180 bottom (schematic designator R60)
R85 "Res1" CR1608-0603 9212,8890 r180 bottom (schematic designator R20)
R86 "Res1" CR1608-0603 9212,8690 r180 bottom (schematic designator R53)
R87 "Res1" CR1608-0603 9212,8790 r180 bottom (schematic designator R21)
S1 "SW DIP-2" HEADER2X2 4935,6378 r90 top
S2 "SW-PB" BUTTON 7020,8580 r90 top
U1 "EP1C12Q240C6" PQFP240 5606,8254 r180 top locked (schematic designator U2)
U2 "Am29LV800B" TSOP48 5966,6414 r180 top locked (schematic designator U7)
U3 "CYP15G0101" BGA100x10 5676,9553 r0 top locked
U4 "HY57V283220" TSOP86 7106,6834 r270 top locked (schematic designator U8)
U5 "Oscillator   20MHz" OSC 6540,9180 r180 top (schematic designator U6)
U6 "Oscillator   27MHz" OSC 6880,8220 r270 top (schematic designator U4)
U7 "TPS75733" SOT23-5S 7180,9620 r0 top (schematic designator U14)
U8 "TPS3823-33" DBV5 7300,7960 r270 top (schematic designator U18)
U9 "AS1117-1.5V" LM1117 7679,8881 r0 top (schematic designator U16)
U10 "SAA7121H" QFP44_2 7620,8100 r90 top (schematic designator U19)
U11 "TMS320DM642" GNZ548 8966,6834 r0 top (schematic designator U1)
U12 "Oscillator" OSC50MHz 8460,8480 r0 top (schematic designator U23)
U13 "TPS54310" PWP20 8460,9180 r90 top (schematic designator U15)
U14 "ACF451832" ACF451832 8640,8540 r270 top (schematic designator U20)
U15 "Oscillator" OSC50MHz 9000,8460 r0 top (schematic designator U21)
U16 "SN74CBT16210" SSOP48 9500,6920 r180 top (schematic designator U11)
U17 "93C66B" SO-G8 9340,7800 r270 top (schematic designator U22)
U18 "AS1117-2.5V" LM1117 4820,9425 r90 bottom (schematic designator U17)
U19 "EPCS1SI8" SOIC8 6780,8120 r180 bottom (schematic designator U5)
U20 "SN74CBT16210" SSOP48 9500,7400 r180 bottom (schematic designator U10)
U21 "SN74CBT16210" SSOP48 9500,7900 r180 bottom (schematic designator U9)

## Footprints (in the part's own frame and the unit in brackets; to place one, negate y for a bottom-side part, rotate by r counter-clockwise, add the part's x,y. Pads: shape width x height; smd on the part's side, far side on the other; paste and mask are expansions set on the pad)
0603 [mil] "for DSP"
  rect 35x30 smd: 1(0,0) 2(62.99,0)
  silkscreen extent -22,-19 84,19
ACF451832 [mm] "for ACF451832-333-T"
  rect 1.2x2.5 smd: 1(0,0) 2(2.5,0) 3(5,0)
  silkscreen extent -0.76,-1.63 5.79,1.55
BGA100x10 [mm] "for CYP15G0101"
  round 0.45 smd: A1(0,0) A2(1,0) A3(2,0) A4(3,0) A5(4,0) A6(5,0) A7(6,0) A8(7,0) A9(8,0) A10(9,0) B1(0,-1) B2(1,-1) B3(2,-1) B4(3,-1) B5(4,-1) B6(5,-1) B7(6,-1) B8(7,-1) B9(8,-1) B10(9,-1) C1(0,-2) C2(1,-2) C3(2,-2) C4(3,-2) C5(4,-2) C6(5,-2) C7(6,-2) C8(7,-2) C9(8,-2) C10(9,-2) D1(0,-3) D2(1,-3) D3(2,-3) D4(3,-3) D5(4,-3) D6(5,-3) D7(6,-3) D8(7,-3) D9(8,-3) D10(9,-3) E1(0,-4) E2(1,-4) E3(2,-4) E4(3,-4) E5(4,-4) E6(5,-4) E7(6,-4) E8(7,-4) E9(8,-4) E10(9,-4) F1(0,-5) F2(1,-5) F3(2,-5) F4(3,-5) F5(4,-5) F6(5,-5) F7(6,-5) F8(7,-5) F9(8,-5) F10(9,-5) G1(0,-6) G2(1,-6) G3(2,-6) G4(3,-6) G5(4,-6) G6(5,-6) G7(6,-6) G8(7,-6) G9(8,-6) G10(9,-6) H1(0,-7) H2(1,-7) H3(2,-7) H4(3,-7) H5(4,-7) H6(5,-7) H7(6,-7) H8(7,-7) H9(8,-7) H10(9,-7) J1(0,-8) J2(1,-8) J3(2,-8) J4(3,-8) J5(4,-8) J6(5,-8) J7(6,-8) J8(7,-8) J9(8,-8) J10(9,-8) K1(0,-9) K2(1,-9) K3(2,-9) K4(3,-9) K5(4,-9) K6(5,-9) K7(6,-9) K8(7,-9) K9(8,-9) K10(9,-9)
  silkscreen extent -1,-10 10,1
BUTTON [mm]
  rect 1.5x1.5 hole 0.9: 1(-1.27,-3.81)
  round 1.5 hole 0.9: 2(2.98,-3.81) 3(2.98,2.2) 4(-1.27,2.2)
  silkscreen extent -2.34,-4.93 4.04,3.12
C1608-0603 [mm]
  rect 1.1x1 smd: 1(-0.85,0) 2(0.85,0)
  silkscreen extent -1.8,-0.9 1.8,0.9
CC3216-1206 [mm]
  rect 1.6x1.8 smd: 1(-1.4,0) 2(1.4,0)
  silkscreen extent -2.6,-1.3 2.1,1.3
CC6032 [mm] "for 100uF"
  rect 2x3.5 smd: 1(0,0) 2(6,0)
  silkscreen extent -1.56,-2.03 7.34,2.01
CR1608-0603 [mm]
  rect 1.1x1 smd: 1(-0.85,0) 2(0.85,0)
  silkscreen extent -1.8,-0.9 1.8,0.9
DBV5 [mm] "DBV5;DBV (R-PDSO-G5);PSO;for TPS3823-33"
  rect 2x0.6 smd: 1(0,0)
  oval 2x0.6 smd: 2(0,-0.95) 3(0,-1.9) 4(3,-1.9) 5(3,0)
  silkscreen extent -1.27,-2.41 4.45,0.48
GNZ548 [mm] "BGA;548 Balls;Body 27 x 27 mm;for DM642"
  round 0.47 smd: A1(0,0) A2(-1,0) A3(-2,0) A4(-3,0) A5(-4,0) A6(-5,0) A7(-6,0) A8(-7,0) A9(-8,0) A10(-9,0) A11(-10,0) A12(-11,0) A13(-12,0) A14(-13,0) A15(-14,0) A16(-15,0) A17(-16,0) A18(-17,0) A19(-18,0) A20(-19,0) A21(-20,0) A22(-21,0) A23(-22,0) A24(-23,0) A25(-24,0) A26(-25,0) AA1(0,20) AA2(-1,20) AA3(-2,20) AA4(-3,20) AA5(-4,20) AA6(-5,20) AA7(-6,20) AA8(-7,20) AA9(-8,20) AA10(-9,20) AA11(-10,20) AA12(-11,20) AA13(-12,20) AA14(-13,20) AA15(-14,20) AA16(-15,20) AA17(-16,20) AA18(-17,20) AA19(-18,20) AA20(-19,20) AA21(-20,20) AA22(-21,20) AA23(-22,20) AA24(-23,20) AA25(-24,20) AA26(-25,20) AB1(0,21) AB2(-1,21) AB3(-2,21) AB4(-3,21) AB5(-4,21) AB6(-5,21) AB7(-6,21) AB8(-7,21) AB9(-8,21) AB10(-9,21) AB11(-10,21) AB12(-11,21) AB13(-12,21) AB14(-13,21) AB15(-14,21) AB16(-15,21) AB17(-16,21) AB18(-17,21) AB19(-18,21) AB20(-19,21) AB21(-20,21) AB22(-21,21) AB23(-22,21) AB24(-23,21) AB25(-24,21) AB26(-25,21) AC1(0,22) AC2(-1,22) AC3(-2,22) AC4(-3,22) AC5(-4,22) AC6(-5,22) AC7(-6,22) AC8(-7,22) AC9(-8,22) AC10(-9,22) AC11(-10,22) AC12(-11,22) AC13(-12,22) AC14(-13,22) AC15(-14,22) AC16(-15,22) AC17(-16,22) AC18(-17,22) AC19(-18,22) AC20(-19,22) AC21(-20,22) AC22(-21,22) AC23(-22,22) AC24(-23,22) AC25(-24,22) AC26(-25,22) AD1(0,23) AD2(-1,23) AD3(-2,23) AD4(-3,23) AD5(-4,23) AD6(-5,23) AD7(-6,23) AD8(-7,23) AD9(-8,23) AD10(-9,23) AD11(-10,23) AD12(-11,23) AD13(-12,23) AD14(-13,23) AD15(-14,23) AD16(-15,23) AD17(-16,23) AD18(-17,23) AD19(-18,23) AD20(-19,23) AD21(-20,23) AD22(-21,23) AD23(-22,23) AD24(-23,23) AD25(-24,23) AD26(-25,23) AE1(0,24) AE2(-1,24) AE3(-2,24) AE4(-3,24) AE5(-4,24) AE6(-5,24) AE7(-6,24) AE8(-7,24) AE9(-8,24) AE10(-9,24) AE11(-10,24) AE12(-11,24) AE13(-12,24) AE14(-13,24) AE15(-14,24) AE16(-15,24) AE17(-16,24) AE18(-17,24) AE19(-18,24) AE20(-19,24) AE21(-20,24) AE22(-21,24) AE23(-22,24) AE24(-23,24) AE25(-24,24) AE26(-25,24) AF1(0,25) AF2(-1,25) AF3(-2,25) AF4(-3,25) AF5(-4,25) AF6(-5,25) AF7(-6,25) AF8(-7,25) AF9(-8,25) AF10(-9,25) AF11(-10,25) AF12(-11,25) AF13(-12,25) AF14(-13,25) AF15(-14,25) AF16(-15,25) AF17(-16,25) AF18(-17,25) AF19(-18,25) AF20(-19,25) AF21(-20,25) AF22(-21,25) AF23(-22,25) AF24(-23,25) AF25(-24,25) AF26(-25,25) B1(0,1) B2(-1,1) B3(-2,1) B4(-3,1) B5(-4,1) B6(-5,1) B7(-6,1) B8(-7,1) B9(-8,1) B10(-9,1) B11(-10,1) B12(-11,1) B13(-12,1) B14(-13,1) B15(-14,1) B16(-15,1) B17(-16,1) B18(-17,1) B19(-18,1) B20(-19,1) B21(-20,1) B22(-21,1) B23(-22,1) B24(-23,1) B25(-24,1) B26(-25,1) C1(0,2) C2(-1,2) C3(-2,2) C4(-3,2) C5(-4,2) C6(-5,2) C7(-6,2) C8(-7,2) C9(-8,2) C10(-9,2) C11(-10,2) C12(-11,2) C13(-12,2) C14(-13,2) C15(-14,2) C16(-15,2) C17(-16,2) C18(-17,2) C19(-18,2) C20(-19,2) C21(-20,2) C22(-21,2) C23(-22,2) C24(-23,2) C25(-24,2) C26(-25,2) D1(0,3) D2(-1,3) D3(-2,3) D4(-3,3) D5(-4,3) D6(-5,3) D7(-6,3) D8(-7,3) D9(-8,3) D10(-9,3) D11(-10,3) D12(-11,3) D13(-12,3) D14(-13,3) D15(-14,3) D16(-15,3) D17(-16,3) D18(-17,3) D19(-18,3) D20(-19,3) D21(-20,3) D22(-21,3) D23(-22,3) D24(-23,3) D25(-24,3) D26(-25,3) E1(0,4) E2(-1,4) E3(-2,4) E4(-3,4) E5(-4,4) E6(-5,4) E7(-6,4) E8(-7,4) E9(-8,4) E10(-9,4) E11(-10,4) E12(-11,4) E13(-12,4) E14(-13,4) E15(-14,4) E16(-15,4) E17(-16,4) E18(-17,4) E19(-18,4) E20(-19,4) E21(-20,4) E22(-21,4) E23(-22,4) E24(-23,4) E25(-24,4) E26(-25,4) F1(0,5) F2(-1,5) F3(-2,5) F4(-3,5) F5(-4,5) F6(-5,5) F7(-6,5) F8(-7,5) F9(-8,5) F10(-9,5) F11(-10,5) F12(-11,5) F13(-12,5) F14(-13,5) F15(-14,5) F16(-15,5) F17(-16,5) F18(-17,5) F19(-18,5) F20(-19,5) F21(-20,5) F22(-21,5) F23(-22,5) F24(-23,5) F25(-24,5) F26(-25,5) G1(0,6) G2(-1,6) G3(-2,6) G4(-3,6) G5(-4,6) G6(-5,6) G7(-6,6) G8(-7,6) G9(-8,6) G10(-9,6) G11(-10,6) G12(-11,6) G13(-12,6) G14(-13,6) G15(-14,6) G16(-15,6) G17(-16,6) G18(-17,6) G19(-18,6) G20(-19,6) G21(-20,6) G22(-21,6) G23(-22,6) G24(-23,6) G25(-24,6) G26(-25,6) H1(0,7) H2(-1,7) H3(-2,7) H4(-3,7) H5(-4,7) H6(-5,7) H7(-6,7) H20(-19,7) H21(-20,7) H22(-21,7) H23(-22,7) H24(-23,7) H25(-24,7) H26(-25,7) J1(0,8) J2(-1,8) J3(-2,8) J4(-3,8) J5(-4,8) J6(-5,8) J7(-6,8) J20(-19,8) J21(-20,8) J22(-21,8) J23(-22,8) J24(-23,8) J25(-24,8) J26(-25,8) K1(0,9) K2(-1,9) K3(-2,9) K4(-3,9) K5(-4,9) K6(-5,9) K7(-6,9) K20(-19,9) K21(-20,9) K22(-21,9) K23(-22,9) K24(-23,9) K25(-24,9) K26(-25,9) L1(0,10) L2(-1,10) L3(-2,10) L4(-3,10) L5(-4,10) L6(-5,10) L7(-6,10) L20(-19,10) L21(-20,10) L22(-21,10) L23(-22,10) L24(-23,10) L25(-24,10) L26(-25,10) M1(0,11) M2(-1,11) M3(-2,11) M4(-3,11) M5(-4,11) M6(-5,11) M7(-6,11) M12(-11,11) M13(-12,11) M14(-13,11) M15(-14,11) M20(-19,11) M21(-20,11) M22(-21,11) M23(-22,11) M24(-23,11) M25(-24,11) M26(-25,11) N1(0,12) N2(-1,12) N3(-2,12) N4(-3,12) N5(-4,12) N6(-5,12) N7(-6,12) N12(-11,12) N13(-12,12) N14(-13,12) N15(-14,12) N20(-19,12) N21(-20,12) N22(-21,12) N23(-22,12) N24(-23,12) N25(-24,12) N26(-25,12) P1(0,13) P2(-1,13) P3(-2,13) P4(-3,13) P5(-4,13) P6(-5,13) P7(-6,13) P12(-11,13) P13(-12,13) P14(-13,13) P15(-14,13) P20(-19,13) P21(-20,13) P22(-21,13) P23(-22,13) P24(-23,13) P25(-24,13) P26(-25,13) R1(0,14) R2(-1,14) R3(-2,14) R4(-3,14) R5(-4,14) R6(-5,14) R7(-6,14) R12(-11,14) R13(-12,14) R14(-13,14) R15(-14,14) R20(-19,14) R21(-20,14) R22(-21,14) R23(-22,14) R24(-23,14) R25(-24,14) R26(-25,14) T1(0,15) T2(-1,15) T3(-2,15) T4(-3,15) T5(-4,15) T6(-5,15) T7(-6,15) T20(-19,15) T21(-20,15) T22(-21,15) T23(-22,15) T24(-23,15) T25(-24,15) T26(-25,15) U1(0,16) U2(-1,16) U3(-2,16) U4(-3,16) U5(-4,16) U6(-5,16) U7(-6,16) U20(-19,16) U21(-20,16) U22(-21,16) U23(-22,16) U24(-23,16) U25(-24,16) U26(-25,16) V1(0,17) V2(-1,17) V3(-2,17) V4(-3,17) V5(-4,17) V6(-5,17) V7(-6,17) V20(-19,17) V21(-20,17) V22(-21,17) V23(-22,17) V24(-23,17) V25(-24,17) V26(-25,17) W1(0,18) W2(-1,18) W3(-2,18) W4(-3,18) W5(-4,18) W6(-5,18) W7(-6,18) W20(-19,18) W21(-20,18) W22(-21,18) W23(-22,18) W24(-23,18) W25(-24,18) W26(-25,18) Y1(0,19) Y2(-1,19) Y3(-2,19) Y4(-3,19) Y5(-4,19) Y6(-5,19) Y7(-6,19) Y8(-7,19) Y9(-8,19) Y10(-9,19) Y11(-10,19) Y12(-11,19) Y13(-12,19) Y14(-13,19) Y15(-14,19) Y16(-15,19) Y17(-16,19) Y18(-17,19) Y19(-18,19) Y20(-19,19) Y21(-20,19) Y22(-21,19) Y23(-22,19) Y24(-23,19) Y25(-24,19) Y26(-25,19)
  silkscreen extent -26,-1.02 1.8,26
HDR1X2 [mm] "Connector; Header; 2 Position"
  rect 1.5x1.5 hole 0.9: 1(0,0)
  round 1.5 hole 0.9: 2(2.54,0)
  silkscreen extent -1.27,-1.27 3.81,1.27
HDR2X2 [mm] "Connector; Header; 2x2 Position"
  rect 1.5x1.5 hole 0.9: 1(0,0)
  round 1.5 hole 0.9: 2(0,2.54) 3(2.54,0) 4(2.54,2.54)
  silkscreen extent -1.27,-1.27 3.81,3.81
HDR2X5 [mil]
  oct 62x62 hole 35: 1(0,0)
  round 62 hole 35: 2(0,100) 3(100,0) 4(100,100) 5(200,0) 6(200,100) 7(300,0) 8(300,100) 9(400,0) 10(400,100)
  silkscreen extent -50,-50 450,150
HDR2X6 [mm] "Connector; Header; 6x2 Position"
  rect 1.5x1.5 hole 0.9: 1(0,0)
  round 1.5 hole 0.9: 2(0,2.54) 3(2.54,0) 4(2.54,2.54) 5(5.08,0) 6(5.08,2.54) 7(7.62,0) 8(7.62,2.54) 9(10.16,0) 10(10.16,2.54) 11(12.7,0) 12(12.7,2.54)
  silkscreen extent -1.27,-1.27 13.97,3.81
HDR2X7 [mm] "Connector; Header; 7x2 Position"
  rect 1.5x1.5 hole 0.9: 1(0,0)
  round 1.5 hole 0.9: 2(0,2.54) 3(2.54,0) 4(2.54,2.54) 5(5.08,0) 6(5.08,2.54) 7(7.62,0) 8(7.62,2.54) 9(10.16,0) 10(10.16,2.54) 11(12.7,0) 12(12.7,2.54) 13(15.24,0) 14(15.24,2.54)
  silkscreen extent -1.27,-1.27 16.51,3.81
HEADER2X2 [mm]
  rect 1.5x1.5 hole 0.9: 1(0,0)
  round 1.5 hole 0.9: 2(0,2.54) 3(2.54,0) 4(2.54,2.54)
  silkscreen extent -1.27,-1.27 3.81,3.81
L44.7uH [mm] "for L4"
  rect 3.5x3.5 smd: 1(0,0) 2(10,0)
  silkscreen extent -1.78,-5 11.81,5
LM1117 [mil]
  rect 90x42 smd: 1(-250,141)
  oval 90x42 smd: 2(-250,51) 3(-250,-39)
  rect 100x130 smd: 4(-20,51)
  silkscreen extent -184,-84 -85,186
OSC [mm]
  rect 2x3 smd: 1(-5,2.134) 2(-5,-2.87) 3(0,-2.866) 4(0,2.134)
  silkscreen extent -6.22,-4.52 1.19,4.48
OSC50MHz [mm] "for 50MHz"
  rect 2x3 smd: 1(-5,2.134) 2(-5,-2.87) 3(0,-2.866) 4(0,2.134)
  silkscreen extent -6.22,-4.52 1.19,4.48
PCI2-H121 [mm]
  round 1.3 hole 0.7: A1(21,-5) A2(19,-5) A3(17,-5) A4(15,-5) A5(13,-5) A6(11,-5) A7(9,-5) A8(7,-5) A9(5,-5) A10(3,-5) A11(1,-5) A12(-1,-5) A13(-3,-5) A14(-5,-5) A15(-7,-5) A16(-9,-5) A17(-11,-5) A18(-13,-5) A19(-15,-5) A20(-17,-5) A21(-19,-5) A22(-21,-5) B1(21,-3) B2(19,-3) B3(17,-3) B4(15,-3) B5(13,-3) B6(11,-3) B7(9,-3) B8(7,-3) B9(5,-3) B10(3,-3) B11(1,-3) B12(-1,-3) B13(-3,-3) B14(-5,-3) B15(-7,-3) B16(-9,-3) B17(-11,-3) B18(-13,-3) B19(-15,-3) B20(-17,-3) B21(-19,-3) B22(-21,-3) C1(21,-1) C2(19,-1) C3(17,-1) C4(15,-1) C5(13,-1) C6(11,-1) C7(9,-1) C8(7,-1) C9(5,-1) C10(3,-1) C11(1,-1) C12(-1,-1) C13(-3,-1) C14(-5,-1) C15(-7,-1) C16(-9,-1) C17(-11,-1) C18(-13,-1) C19(-15,-1) C20(-17,-1) C21(-19,-1) C22(-21,-1) D1(21,1) D2(19,1) D3(17,1) D4(15,1) D5(13,1) D6(11,1) D7(9,1) D8(7,1) D9(5,1) D10(3,1) D11(1,1) D12(-1,1) D13(-3,1) D14(-5,1) D15(-7,1) D16(-9,1) D17(-11,1) D18(-13,1) D19(-15,1) D20(-17,1) D21(-19,1) D22(-21,1) E1(21,3) E2(19,3) E3(17,3) E4(15,3) E5(13,3) E6(11,3) E7(9,3) E8(7,3) E9(5,3) E10(3,3) E11(1,3) E12(-1,3) E13(-3,3) E14(-5,3) E15(-7,3) E16(-9,3) E17(-11,3) E18(-13,3) E19(-15,3) E20(-17,3) E21(-19,3) E22(-21,3) F1(21,5) F3(17,5) F5(13,5) F7(9,5) F9(5,5) F11(1,5) F13(-3,5) F15(-7,5) F17(-11,5) F19(-15,5) F21(-19,5)
  silkscreen extent -22,-6.5 20.93,6.05
PCI2-H123 [mm]
  round 1.3 hole 0.7: A1(24,-5) A2(22,-5) A3(20,-5) A4(18,-5) A5(16,-5) A6(14,-5) A7(12,-5) A8(10,-5) A9(8,-5) A10(6,-5) A11(4,-5) A15(-4,-5) A16(-6,-5) A17(-8,-5) A18(-10,-5) A19(-12,-5) A20(-14,-5) A21(-16,-5) A22(-18,-5) A23(-20,-5) A24(-22,-5) A25(-24,-5) B1(24,-3) B2(22,-3) B3(20,-3) B4(18,-3) B5(16,-3) B6(14,-3) B7(12,-3) B8(10,-3) B9(8,-3) B10(6,-3) B11(4,-3) B15(-4,-3) B16(-6,-3) B17(-8,-3) B18(-10,-3) B19(-12,-3) B20(-14,-3) B21(-16,-3) B22(-18,-3) B23(-20,-3) B24(-22,-3) B25(-24,-3) C1(24,-1) C2(22,-1) C3(20,-1) C4(18,-1) C5(16,-1) C6(14,-1) C7(12,-1) C8(10,-1) C9(8,-1) C10(6,-1) C11(4,-1) C15(-4,-1) C16(-6,-1) C17(-8,-1) C18(-10,-1) C19(-12,-1) C20(-14,-1) C21(-16,-1) C22(-18,-1) C23(-20,-1) C24(-22,-1) C25(-24,-1) D1(24,1) D2(22,1) D3(20,1) D4(18,1) D5(16,1) D6(14,1) D7(12,1) D8(10,1) D9(8,1) D10(6,1) D11(4,1) D15(-4,1) D16(-6,1) D17(-8,1) D18(-10,1) D19(-12,1) D20(-14,1) D21(-16,1) D22(-18,1) D23(-20,1) D24(-22,1) D25(-24,1) E1(24,3) E2(22,3) E3(20,3) E4(18,3) E5(16,3) E6(14,3) E7(12,3) E8(10,3) E9(8,3) E10(6,3) E11(4,3) E15(-4,3) E16(-6,3) E17(-8,3) E18(-10,3) E19(-12,3) E20(-14,3) E21(-16,3) E22(-18,3) E23(-20,3) E24(-22,3) E25(-24,3) F1(24,5) F3(20,5) F5(16,5) F7(12,5) F9(8,5) F11(4,5) F13(0,5) F15(-4,5) F17(-8,5) F19(-12,5) F21(-16,5) F23(-20,5) F25(-24,5)
  silkscreen extent -24.03,-6.5 25,6.1
POWER_CON [mm] "for power input"
  rect 3.8x3.8 hole 2.5: 1(0,0) 2(6.5,0) 3(3.25,4.5)
  silkscreen extent -1.98,-3.56 13.31,6.78
PQFP240 [mm] "240-Pin Plastic Quad Flat Pack (PQFP)"
  rect 1.5x0.3 smd: 1(-16.975,14.75) 2(-16.975,14.25) 3(-16.975,13.75) 4(-16.975,13.25) 5(-16.975,12.75) 6(-16.975,12.25) 7(-16.975,11.75) 8(-16.975,11.25) 9(-16.975,10.75) 10(-16.975,10.25) 11(-16.975,9.75) 12(-16.975,9.25) 13(-16.975,8.75) 14(-16.975,8.25) 15(-16.975,7.75) 16(-16.975,7.25) 17(-16.975,6.75) 18(-16.975,6.25) 19(-16.975,5.75) 20(-16.975,5.25) 21(-16.975,4.75) 22(-16.975,4.25) 23(-16.975,3.75) 24(-16.975,3.25) 25(-16.975,2.75) 26(-16.975,2.25) 27(-16.975,1.75) 28(-16.975,1.25) 29(-16.975,0.75) 30(-16.975,0.25) 31(-16.975,-0.25) 32(-16.975,-0.75) 33(-16.975,-1.25) 34(-16.975,-1.75) 35(-16.975,-2.25) 36(-16.975,-2.75) 37(-16.975,-3.25) 38(-16.975,-3.75) 39(-16.975,-4.25) 40(-16.975,-4.75) 41(-16.975,-5.25) 42(-16.975,-5.75) 43(-16.975,-6.25) 44(-16.975,-6.75) 45(-16.975,-7.25) 46(-16.975,-7.75) 47(-16.975,-8.25) 48(-16.975,-8.75) 49(-16.975,-9.25) 50(-16.975,-9.75) 51(-16.975,-10.25) 52(-16.975,-10.75) 53(-16.975,-11.25) 54(-16.975,-11.75) 55(-16.975,-12.25) 56(-16.975,-12.75) 57(-16.975,-13.25) 58(-16.975,-13.75) 59(-16.975,-14.25) 60(-16.975,-14.75) 121(16.975,-14.75) 122(16.975,-14.25) 123(16.975,-13.75) 124(16.975,-13.25) 125(16.975,-12.75) 126(16.975,-12.25) 127(16.975,-11.75) 128(16.975,-11.25) 129(16.975,-10.75) 130(16.975,-10.25) 131(16.975,-9.75) 132(16.975,-9.25) 133(16.975,-8.75) 134(16.975,-8.25) 135(16.975,-7.75) 136(16.975,-7.25) 137(16.975,-6.75) 138(16.975,-6.25) 139(16.975,-5.75) 140(16.975,-5.25) 141(16.975,-4.75) 142(16.975,-4.25) 143(16.975,-3.75) 144(16.975,-3.25) 145(16.975,-2.75) 146(16.975,-2.25) 147(16.975,-1.75) 148(16.975,-1.25) 149(16.975,-0.75) 150(16.975,-0.25) 151(16.975,0.25) 152(16.975,0.75) 153(16.975,1.25) 154(16.975,1.75) 155(16.975,2.25) 156(16.975,2.75) 157(16.975,3.25) 158(16.975,3.75) 159(16.975,4.25) 160(16.975,4.75) 161(16.975,5.25) 162(16.975,5.75) 163(16.975,6.25) 164(16.975,6.75) 165(16.975,7.25) 166(16.975,7.75) 167(16.975,8.25) 168(16.975,8.75) 169(16.975,9.25) 170(16.975,9.75) 171(16.975,10.25) 172(16.975,10.75) 173(16.975,11.25) 174(16.975,11.75) 175(16.975,12.25) 176(16.975,12.75) 177(16.975,13.25) 178(16.975,13.75) 179(16.975,14.25) 180(16.975,14.75)
  rect 0.3x1.5 smd: 61(-14.75,-16.975) 62(-14.25,-16.975) 63(-13.75,-16.975) 64(-13.25,-16.975) 65(-12.75,-16.975) 66(-12.25,-16.975) 67(-11.75,-16.975) 68(-11.25,-16.975) 69(-10.75,-16.975) 70(-10.25,-16.975) 71(-9.75,-16.975) 72(-9.25,-16.975) 73(-8.75,-16.975) 74(-8.25,-16.975) 75(-7.75,-16.975) 76(-7.25,-16.975) 77(-6.75,-16.975) 78(-6.25,-16.975) 79(-5.75,-16.975) 80(-5.25,-16.975) 81(-4.75,-16.975) 82(-4.25,-16.975) 83(-3.75,-16.975) 84(-3.25,-16.975) 85(-2.75,-16.975) 86(-2.25,-16.975) 87(-1.75,-16.975) 88(-1.25,-16.975) 89(-0.75,-16.975) 90(-0.25,-16.975) 91(0.25,-16.975) 92(0.75,-16.975) 93(1.25,-16.975) 94(1.75,-16.975) 95(2.25,-16.975) 96(2.75,-16.975) 97(3.25,-16.975) 98(3.75,-16.975) 99(4.25,-16.975) 100(4.75,-16.975) 101(5.25,-16.975) 102(5.75,-16.975) 103(6.25,-16.975) 104(6.75,-16.975) 105(7.25,-16.975) 106(7.75,-16.975) 107(8.25,-16.975) 108(8.75,-16.975) 109(9.25,-16.975) 110(9.75,-16.975) 111(10.25,-16.975) 112(10.75,-16.975) 113(11.25,-16.975) 114(11.75,-16.975) 115(12.25,-16.975) 116(12.75,-16.975) 117(13.25,-16.975) 118(13.75,-16.975) 119(14.25,-16.975) 120(14.75,-16.975) 181(14.75,16.975) 182(14.25,16.975) 183(13.75,16.975) 184(13.25,16.975) 185(12.75,16.975) 186(12.25,16.975) 187(11.75,16.975) 188(11.25,16.975) 189(10.75,16.975) 190(10.25,16.975) 191(9.75,16.975) 192(9.25,16.975) 193(8.75,16.975) 194(8.25,16.975) 195(7.75,16.975) 196(7.25,16.975) 197(6.75,16.975) 198(6.25,16.975) 199(5.75,16.975) 200(5.25,16.975) 201(4.75,16.975) 202(4.25,16.975) 203(3.75,16.975) 204(3.25,16.975) 205(2.75,16.975) 206(2.25,16.975) 207(1.75,16.975) 208(1.25,16.975) 209(0.75,16.975) 210(0.25,16.975) 211(-0.25,16.975) 212(-0.75,16.975) 213(-1.25,16.975) 214(-1.75,16.975) 215(-2.25,16.975) 216(-2.75,16.975) 217(-3.25,16.975) 218(-3.75,16.975) 219(-4.25,16.975) 220(-4.75,16.975) 221(-5.25,16.975) 222(-5.75,16.975) 223(-6.25,16.975) 224(-6.75,16.975) 225(-7.25,16.975) 226(-7.75,16.975) 227(-8.25,16.975) 228(-8.75,16.975) 229(-9.25,16.975) 230(-9.75,16.975) 231(-10.25,16.975) 232(-10.75,16.975) 233(-11.25,16.975) 234(-11.75,16.975) 235(-12.25,16.975) 236(-12.75,16.975) 237(-13.25,16.975) 238(-13.75,16.975) 239(-14.25,16.975) 240(-14.75,16.975)
  silkscreen extent -17.1,-15.83 15.83,15.83
PWP20 [mm] "PWP20;PSO;PWP (R-PDSO-G**);for TPS54310"
  rect 2x0.4 smd: 1(0,0)
  rect 2.032x3.81 smd: 1(3.302,-2.921)
  oval 2x0.4 smd: 2(0,-0.65) 3(0,-1.3) 4(0,-1.95) 5(0,-2.6) 6(0,-3.25) 7(0,-3.9) 8(0,-4.55) 9(0,-5.2) 10(0,-5.85)
  oval 2.2x0.4 smd: 11(6.6,-5.85) 12(6.6,-5.2) 13(6.6,-4.55) 14(6.6,-3.9) 15(6.6,-3.25) 16(6.6,-2.6) 17(6.6,-1.95) 18(6.6,-1.3) 19(6.6,-0.65) 20(6.6,0)
  silkscreen extent 2.08,-6.18 4.51,0.33
QFP44_2 [mm]
  oval 2.5x0.4 smd: 1(0,0)
  rect 2.5x0.4 smd: 2(0,-0.8) 3(0,-1.6) 4(0,-2.4) 5(0,-3.2) 6(0,-4) 7(0,-4.8) 8(0,-5.6) 9(0,-6.4) 10(0,-7.2) 11(0,-8) 23(12.9,-8) 24(12.9,-7.2) 25(12.9,-6.4) 26(12.9,-5.6) 27(12.9,-4.8) 28(12.9,-4) 29(12.9,-3.2) 30(12.9,-2.4) 31(12.9,-1.6) 32(12.9,-0.8) 33(12.9,0)
  rect 0.4x2.5 smd: 12(2.45,-10.45) 13(3.25,-10.45) 14(4.05,-10.45) 15(4.85,-10.45) 16(5.65,-10.45) 17(6.45,-10.45) 18(7.25,-10.45) 19(8.05,-10.45) 20(8.85,-10.45) 21(9.65,-10.45) 22(10.45,-10.45) 34(10.45,2.45) 35(9.65,2.45) 36(8.85,2.45) 37(8.05,2.45) 38(7.25,2.45) 39(6.45,2.45) 40(5.65,2.45) 41(4.85,2.45) 42(4.05,2.45) 43(3.25,2.45) 44(2.45,2.45)
  silkscreen extent 1.78,-8.67 11.12,0.66
R0603_4 [mil] "for ResPackX4____OK!"
  rect 35x18 smd: 1(0,0) 2(0,-36) 3(0,-72) 4(0,-108) 5(70.16,-108) 6(70.16,-72) 7(70.16,-36) 8(70.16,0)
  silkscreen extent -33,-123 99,15
RCA [mm]
  round 3.5 hole 2.1: 1(4.433,-1.168) 1(4.433,2.832) 2(-1.067,-1.168)
  silkscreen extent -6.91,-6.2 6.43,4.83
SMA [mm]
  round 3 hole 1.8: 1(0,0) 2(-2.5,-2.5) 2(-2.5,2.5) 2(2.5,-2.5) 2(2.5,2.5)
  silkscreen extent -4.5,-4.8 4.5,4.6
"SMD _LED" [mm]
  rect 1.3x1.6 smd: 1(0.95,0) 2(-0.95,0)
  silkscreen extent -2.13,-1.15 2,1.15
"SO-G3 for NPN" [mm]
  rect 0.9x1.27 smd: 1(0,1.25)
  rect 0.9x0.95 smd: 2(-0.95,-1.25) 3(0.95,-1.25)
  silkscreen extent -2.07,-1.37 1.3,1.25
SO-G8 [mm]
  rect 0.6x2.2 smd: 1(-1.905,-2.6) 2(-0.635,-2.6) 3(0.635,-2.6) 4(1.905,-2.6) 5(1.905,2.6) 6(0.635,2.6) 7(-0.635,2.6) 8(-1.905,2.6)
  silkscreen extent -2.88,-2.72 2.5,1.1
SOIC8 [mm] "8-Pin Small-Outline Integrated Circuit (SOIC)"
  rect 0.6x2.2 smd: 1(-1.905,-2.6) 2(-0.635,-2.6) 3(0.635,-2.6) 4(1.905,-2.6) 5(1.905,2.6) 6(0.635,2.6) 7(-0.635,2.6) 8(-1.905,2.6)
  silkscreen extent -2.88,-2.72 2.5,1.1
SOT23-5S [mil] "for TPS75733"
  oval 200x50 smd: 1(0,0) 2(0,-67) 3(0,-134) 4(0,-201) 5(0,-268)
  rect 400x400 smd: 3(375,-135)
  silkscreen extent 130,-360 580,95
SSOP48 [mm]
  rect 2x0.28 smd: 1(0,0)
  oval 2x0.28 smd: 2(0,-0.5) 3(0,-1) 4(0,-1.5) 5(0,-2) 6(0,-2.5) 7(0,-3) 8(0,-3.5) 9(0,-4) 10(0,-4.5) 11(0,-5) 12(0,-5.5) 13(0,-6) 14(0,-6.5) 15(0,-7) 16(0,-7.5) 17(0,-8) 18(0,-8.5) 19(0,-9) 20(0,-9.5) 21(0,-10) 22(0,-10.5) 23(0,-11) 24(0,-11.5) 25(8,-11.5) 26(8,-11) 27(8,-10.5) 28(8,-10) 29(8,-9.5) 30(8,-9) 31(8,-8.5) 32(8,-8) 33(8,-7.5) 34(8,-7) 35(8,-6.5) 36(8,-6) 37(8,-5.5) 38(8,-5) 39(8,-4.5) 40(8,-4) 41(8,-3.5) 42(8,-3) 43(8,-2.5) 44(8,-2) 45(8,-1.5) 46(8,-1) 47(8,-0.5) 48(8,0)
  silkscreen extent 1.84,-11.75 6.16,0.25
TSOP48 [mm] "for Am29LV800B"
  rect 2x0.3 smd: 1(0,0)
  oval 2x0.3 smd: 2(0,-0.5) 3(0,-1) 4(0,-1.5) 5(0,-2) 6(0,-2.5) 7(0,-3) 8(0,-3.5) 9(0,-4) 10(0,-4.5) 11(0,-5) 12(0,-5.5) 13(0,-6) 14(0,-6.5) 15(0,-7) 16(0,-7.5) 17(0,-8) 18(0,-8.5) 19(0,-9) 20(0,-9.5) 21(0,-10) 22(0,-10.5) 23(0,-11) 24(0,-11.5) 25(20.2,-11.5) 26(20.2,-11) 27(20.2,-10.5) 28(20.2,-10) 29(20.2,-9.5) 30(20.2,-9) 31(20.2,-8.5) 32(20.2,-8) 33(20.2,-7.5) 34(20.2,-7) 35(20.2,-6.5) 36(20.2,-6) 37(20.2,-5.5) 38(20.2,-5) 39(20.2,-4.5) 40(20.2,-4) 41(20.2,-3.5) 42(20.2,-3) 43(20.2,-2.5) 44(20.2,-2) 45(20.2,-1.5) 46(20.2,-1) 47(20.2,-0.5) 48(20.2,0)
  silkscreen extent 2.08,-11.75 18.12,0.25
TSOP86 [mm] "TSOP;43*2;for HY57V283220"
  rect 2x0.3 smd: 1(0,0)
  oval 2x0.3 smd: 2(0,-0.5) 3(0,-1) 4(0,-1.5) 5(0,-2) 6(0,-2.5) 7(0,-3) 8(0,-3.5) 9(0,-4) 10(0,-4.5) 11(0,-5) 12(0,-5.5) 13(0,-6) 14(0,-6.5) 15(0,-7) 16(0,-7.5) 17(0,-8) 18(0,-8.5) 19(0,-9) 20(0,-9.5) 21(0,-10) 22(0,-10.5) 23(0,-11) 24(0,-11.5) 25(0,-12) 26(0,-12.5) 27(0,-13) 28(0,-13.5) 29(0,-14) 30(0,-14.5) 31(0,-15) 32(0,-15.5) 33(0,-16) 34(0,-16.5) 35(0,-17) 36(0,-17.5) 37(0,-18) 38(0,-18.5) 39(0,-19) 40(0,-19.5) 41(0,-20) 42(0,-20.5) 43(0,-21) 44(11.938,-21) 45(11.938,-20.5) 46(11.938,-20) 47(11.938,-19.5) 48(11.938,-19) 49(11.938,-18.5) 50(11.938,-18) 51(11.938,-17.5) 52(11.938,-17) 53(11.938,-16.5) 54(11.938,-16) 55(11.938,-15.5) 56(11.938,-15) 57(11.938,-14.5) 58(11.938,-14) 59(11.938,-13.5) 60(11.938,-13) 61(11.938,-12.5) 62(11.938,-12) 63(11.938,-11.5) 64(11.938,-11) 65(11.938,-10.5) 66(11.938,-10) 67(11.938,-9.5) 68(11.938,-9) 69(11.938,-8.5) 70(11.938,-8) 71(11.938,-7.5) 72(11.938,-7) 73(11.938,-6.5) 74(11.938,-6) 75(11.938,-5.5) 76(11.938,-5) 77(11.938,-4.5) 78(11.938,-4) 79(11.938,-3.5) 80(11.938,-3) 81(11.938,-2.5) 82(11.938,-2) 83(11.938,-1.5) 84(11.938,-1) 85(11.938,-0.5) 86(11.938,0)
  silkscreen extent -0.22,-21.25 9.85,0.73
